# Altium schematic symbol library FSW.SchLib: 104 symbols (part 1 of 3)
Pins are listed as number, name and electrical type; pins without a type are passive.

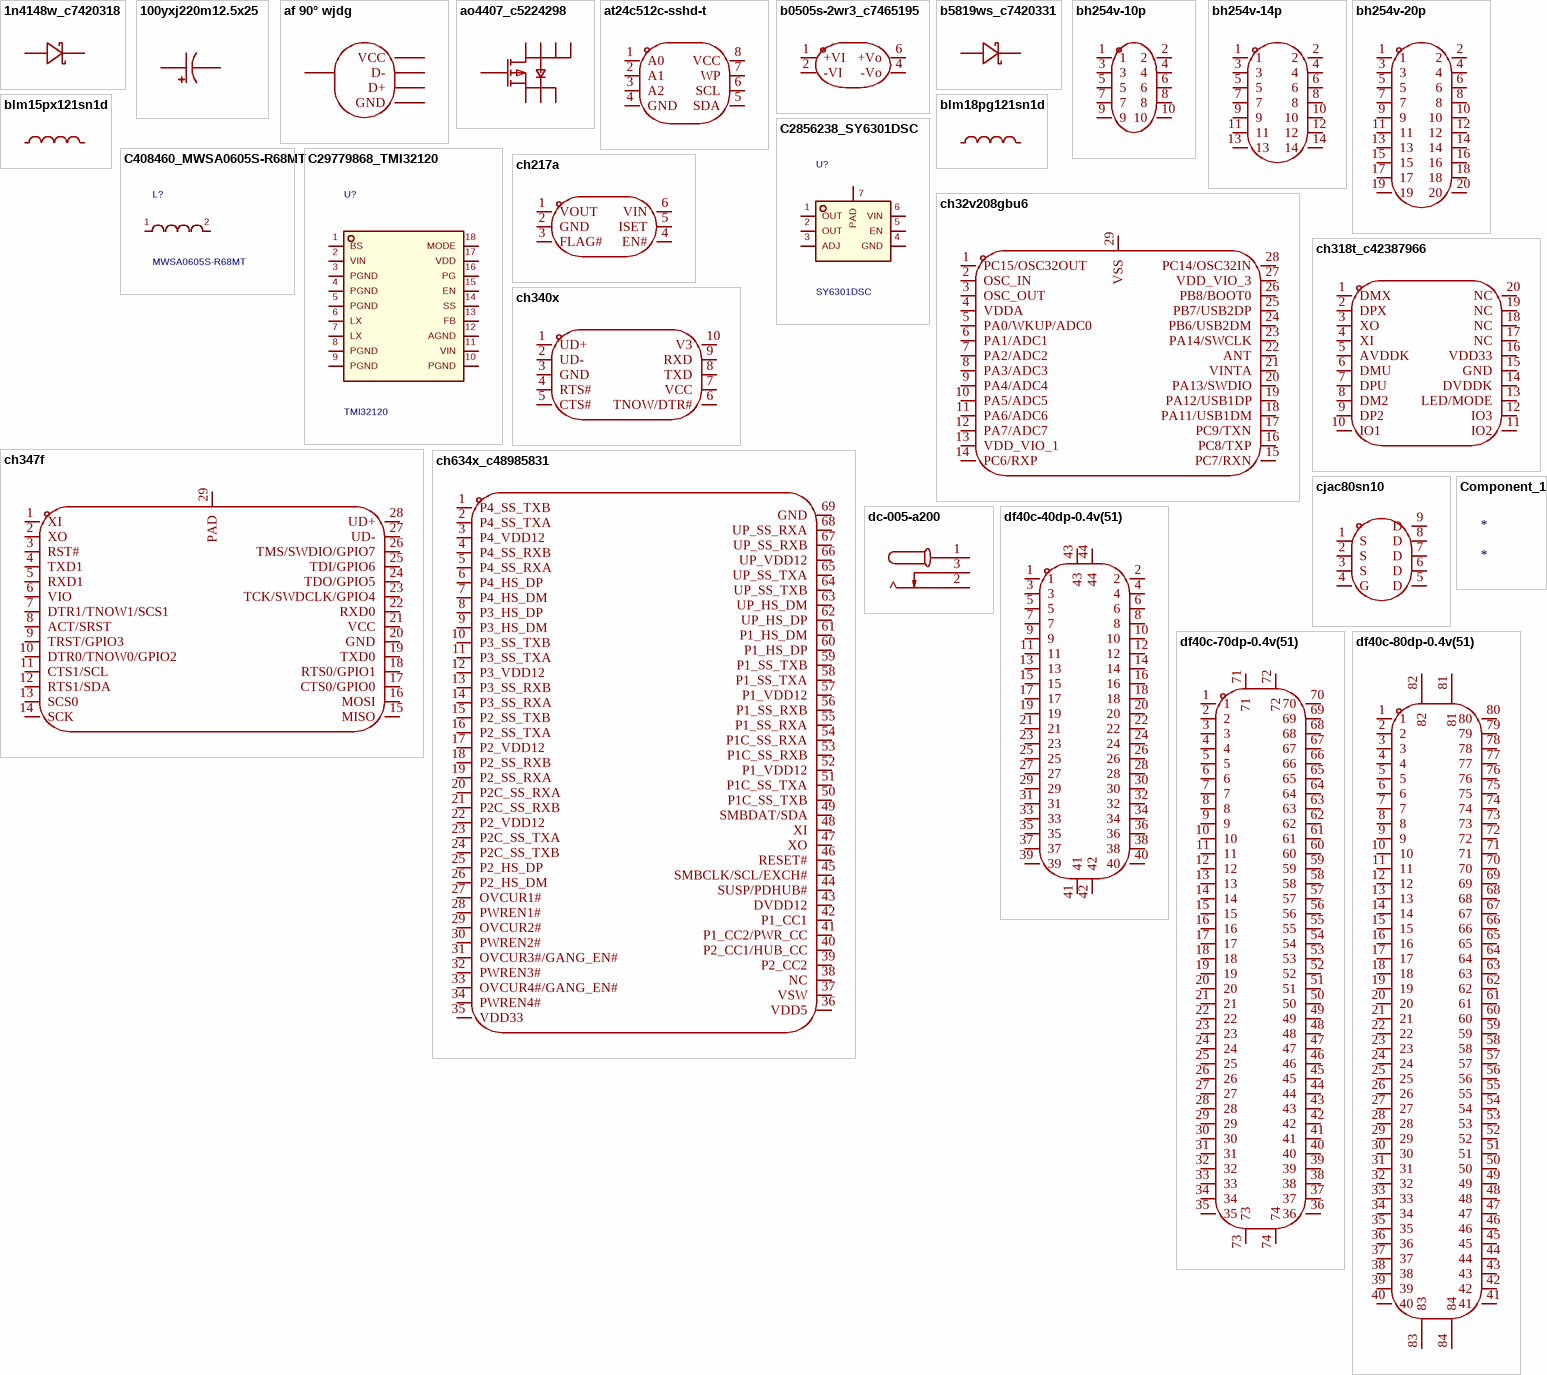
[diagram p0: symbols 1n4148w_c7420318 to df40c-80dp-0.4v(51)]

## 1n4148w_c7420318
designator D??  (value not drawn)
二极管配置:独立式;整流电流:150mA;直流反向耐压(Vr):100V;正向压降(Vf):1.25V@150mA;反向恢复时间(Trr):4ns;; Manufacturer: R+O(宏嘉诚); AddInBom: yes; ModelId: 5054d9b7be8b429dad093a54b517b4dd; ModelName: SOD-123_L2.7-W1.6-LS3.7-FD; ModelTransform: 145.669,61.024,0,0,0,0,0,0,0; Diode Configuration: 独立式; Pd - Power Dissipation: 400mW; Current - Rectified: 150mA; Voltage - DC Reverse(Vr): 100V; Non-Repetitive Peak Forward Surge Current: 2A; Reverse Leakage Current (Ir): 1uA@75V; Reverse Recovery Time (trr): 4ns; Operating Junction Temperature Range: -55℃~+150℃
footprint SOD-123_L2.7-W1.6-LS3.7-FD
pins: 1 A, 2 K

## 100yxj220m12.5x25
designator C??  (value not drawn)
容值:220uF;精度:±20%;额定电压:100V;纹波电流:1.62A@100kHz;等效串联电阻(ESR):-;; Manufacturer: Rubycon(红宝石); AddInBom: yes; ModelId: 968d8ff988964aab8919b46a6a737be2; ModelName: CAP-TH_D12.5-H20.0-P5.00; ModelTransform: 492.5187,492.11201,0,0,0,0,0,0,-137.795; Value: 220uF; Tolerance: ±20%; Voltage Rating: 100V; Pin Spacing: 5mm; Lifetime: 10000hrs@105℃
footprint CAP-TH_BD12.5-P5.00-D0.6-FD
pins: 1, 2

## af 90° wjdg
designator USB??  (value not drawn)
连接器类型:Type-A;协议标准:USB 2.0;公母:母;安装方式:弯插;触点数量:4P;端口数量:1;额定电流 - 电源:1.5A;工作温度:-25℃~+85℃;; Manufacturer: SHOU HAN(首韩); AddInBom: yes; ModelId: 268f7f19b8674295a50f5e7a4a3dee80; ModelName: USB-A-TH_4P-L14.5-W14.0-H7.6-S2.71; ModelTransform: 610.19406,551.18,0,0,0,0,0,-192.915,-149.606; Connector Type: Type-A; Protocol Standard: USB 2.0; Gender: 母; Number of Contacts: 4P; Number of Ports: 1; Current Rating-Power: 1.5A; Voltage Rating: 30V; Connect-Disconnect Life: 5千次; Detection color: 白色
footprint USB-A-TH_AF-WJDG
pins: 1 VCC, 2 D-, 3 D+, 4 GND, 5 SHLD

## ao4407_c5224298
designator Q??  (value not drawn)
数量:1个P沟道;漏源电压(Vdss):30V;连续漏极电流(Id):12A;导通电阻(RDS(on)):9.5mΩ@10V;耗散功率(Pd):3.1W;阈值电压(Vgs(th)):1.5V@250uA;; Manufacturer: ElecSuper(静芯); ManufacturerPart: AO4407; AddInBom: yes; ModelId: ca0cccb852be401a81142c6d2d7c8054; ModelName: SOIC-8_L4.9-W3.8-P1.27-LS6.0-BL; ModelTransform: 192.913,236.22,0,0,0,0,-0.002,0,0; Number: 1个P沟道; Drain to Source Voltage: 30V; Current - Continuous Drain(Id): 12A; Pd - Power Dissipation: 3.1W; Gate Charge(Qg): 46nC@10V; Input Capacitance(Ciss): 1.78nF; Reverse Transfer Capacitance (Crss@Vds): 200pF; Type: P沟道; Output Capacitance(Coss): 235pF
footprint SOIC-8_L4.9-W3.8-P1.27-LS6.0-BL
pins: 1 S, 2 S, 3 S, 4 G, 5 D, 6 D, 7 D, 8 D

## at24c512c-sshd-t
designator U??  (value not drawn)
接口类型:I2C;存储容量:512Kbit;时钟频率(fc):1MHz;; Manufacturer: MICROCHIP(美国微芯); AddInBom: yes; ModelId: e81d2f7d937b4a6ab1dca543ff5d56a4; ModelName: SOIC-8_L4.9-W3.9-H1.7-LS6.0-P1.27; ModelTransform: 192.913,236.22,0,0,0,0,0,0,0; Interface: I2C; Clock Frequency: 1MHz; Write Cycle Time(Tw): 5ms; Data Retention - TDR (Year): 40年; Write Cycle Endurance: 100万次; Voltage - Supply: 2.5V~5.5V
footprint SOIC-8_L4.9-W3.9-P1.27-LS6.0-BL
pins: 1 A0, 2 A1, 3 A2, 4 GND, 5 SDA, 6 SCL, 7 WP, 8 VCC

## b0505s-2wr3_c7465195
designator U??  (value not drawn)
DC-DC隔离电源模块:输入5V(4.5V~5.5V)@@输出5V 400mA 2W@@输出短路保护@@输入输出隔离耐压1.5KV@@SIP7; Manufacturer: EVISUN(易成); AddInBom: yes; ModelId: 14934276571d427a996fe673d734980f; ModelName: PWRM-TH_BXXXXS-2WR3; ModelTransform: 773.6205,277.5585,0,0,0,0,49.409,-102.953,-157.48; Number of Outputs: 1; Output Power: 2W; Conversion Efficiency: 88%; Output Voltage: 5V; Capacitive Load(Max): 2400uF; Isolation Voltage(Vrms): 1.5kV; Value: 200kHz~340kHz; Quiescent Supply Current: 8mA; Ripple Noise: 75mVp-p; Voltage Regulation: 非稳压型
footprint PWRM-TH_BXXXXS-2WR3
pins: 1 +VI, 2 -VI, 4 -Vo, 6 +Vo

## b5819ws_c7420331
designator D??  (value not drawn)
二极管配置:独立式;正向压降(Vf):600mV@1.0A;直流反向耐压(Vr):40V;整流电流:1A;; Manufacturer: R+O(宏嘉诚); AddInBom: yes; ModelId: 0f2f330c645944df9245ac3c3fec3456; ModelName: SOD-323_L1.7-W1.3-LS2.5-FD; ModelTransform: 98.425,49.2125,0,180,0,0,0,0,0; Diode Configuration: 独立式; Voltage - DC Reverse(Vr): 40V; Current - Rectified: 1A; Reverse Leakage Current (Ir): 1mA@40V; Operating Junction Temperature Range: -55℃~+150℃; Non-Repetitive Peak Forward Surge Current: 10A
footprint SOD-323_L1.7-W1.3-LS2.5-FD
pins: 1 A, 2 K

## bh254v-10p
designator CN??  (value not drawn)
连接器类型:简牛座;间距:2.54mm;结构:2x5P;额定电流:3A;额定电压:250V;安装方式:直插;行距:2.54mm;排数:2;每排PIN数:5;工作温度:-40℃~+105℃;; Manufacturer: XFCN(兴飞); AddInBom: yes; ModelId: 46a83b98c0514e7caa52e3945452bfaa; ModelName: IDC-TH_10P-P2.54-V-R2-C5-S2.54; ModelTransform: 799.21498,350.0906,0,0,0,0,0,3.937,-129.921; Connector Type: 简牛座; Pitch: 2.54mm; Number of Positions or Pins: 2x5P; Current Rating: 3A; Voltage Rating (Max): 250V; Holder Type: 直插; Number of PINs Per Row: 5
footprint IDC-TH_10P-P2.54-V-R2-C5-S2.54
pins: 1, 2, 3, 4, 5, 6, 7, 8, 9, 10

## bh254v-14p
designator CN??  (value not drawn)
连接器类型:简牛座;间距:2.54mm;结构:2x7P;额定电流:3A;安装方式:直插;行距:2.54mm;排数:2;每排PIN数:7;触头材质:铜合金;工作温度:-40℃~+105℃;; Manufacturer: XFCN(兴飞); AddInBom: yes; ModelId: 1e191473481d43b08e40c7df32061c8c; ModelName: IDC-TH_14P-P2.54-V-R2-C7-S2.54; ModelTransform: 999.998,348.41478,0,0,0,0,0,3.937,-118.11; Connector Type: 简牛座; Pitch: 2.54mm; Number of Positions or Pins: 2x7P; Current Rating: 3A; Holder Type: 直插; Number of PINs Per Row: 7
footprint IDC-TH_14P-P2.54-V-R2-C7-S2.54
pins: 1, 2, 3, 4, 5, 6, 7, 8, 9, 10, 11, 12, 13, 14

## bh254v-20p
designator CN??  (value not drawn)
连接器类型:简牛座;间距:-;结构:2x10P;额定电流:3A;额定电压:250V;安装方式:直插;行距:2.54mm;排数:2;每排PIN数:10;触头材质:-;触头镀层:-;工作温度:-40℃~+105℃;; Manufacturer: XFCN(兴飞); AddInBom: yes; ModelId: f758914ec7d246748ac341cdbdaac489; ModelName: CONN-TH_20P-P2.54_BH254V-20P; ModelTransform: 1299.214,350.0906,0,0,0,0,0,1.968,-127.953; Connector Type: 简牛座; Number of Positions or Pins: 2x10P; Current Rating: 3A; Voltage Rating (Max): 250V; Holder Type: 直插; Row Spacing: 2.54mm; Number of PINs Per Row: 10
footprint CONN-TH_20P-P2.54_BH254V-20P
pins: 1, 2, 3, 4, 5, 6, 7, 8, 9, 10, 11, 12, 13, 14, 15, 16, 17, 18, 19, 20

## blm15px121sn1d
designator L??  (value not drawn)
阻抗@频率:120Ω@100MHz;误差:±25%;直流电阻(DCR):55mΩ;; Manufacturer: muRata(村田); AddInBom: yes; ModelId: d8d36575a3234d4790bfa765c88664a7; ModelName: L0402_L1.0-W0.5-H0.5_BEAD; ModelTransform: 39.37,19.685,0,0,0,0,0,0.0005,0; Tolerance: ±25%; DC Resistance(DCR): 55mΩ; Current Rating: 2A; Number of Circuits: 1
footprint L0402
pins: 1, 2

## blm18pg121sn1d
designator L??  (value not drawn)
阻抗@频率:120Ω@100MHz;误差:±25%;直流电阻(DCR):50mΩ;; Manufacturer: muRata(村田); Symbol: BLM18PG121SN1D_C14709; AddInBom: yes; ModelId: 2bc5ec593d464d6ba9807aec0b5673c2; ModelName: L0603_L1.6-W0.8-H0.5_BEAD; ModelTransform: 62.992,31.496,0,180,0,0,0.094,0.629,0; Tolerance: ±25%; DC Resistance(DCR): 50mΩ; Current Rating: 2A; Number of Circuits: 1
footprint L0603
pins: 1, 2

## C408460_MWSA0605S-R68MT
designator L?, comment MWSA0605S-R68MT
MWSA0605S-R68MT [C408460]; Manufacturer: Sunlord(顺络); Symbol: C408460_MWSA0605S-R68MT; Value: 680nH; Library Source: JLCEDA/EasyEDA Official Library; https://lceda.cn/ ; https://easyeda.com/
footprint C408460_IND-SMD_L7_0-W6_6
pins: 1, 2

## C2856238_SY6301DSC
designator U?, comment SY6301DSC
SY6301DSC [C2856238]; Manufacturer: Silergy(矽力杰); Symbol: C2856238_SY6301DSC; Library Source: JLCEDA/EasyEDA Official Library; https://lceda.cn/ ; https://easyeda.com/
footprint C2856238_WDFN-6_L3_0-W3_0-P0_95
pins: 1 OUT, 2 OUT, 3 ADJ, 4 GND, 5 EN, 6 VIN, 7 PAD

## C29779868_TMI32120
designator U?, comment TMI32120
TMI32120 [C29779868]; Manufacturer: TMI(拓尔微); Symbol: C29779868_TMI32120; Library Source: JLCEDA/EasyEDA Official Library; https://lceda.cn/ ; https://easyeda.com/
footprint C29779868_VQFN-18_L3_5-W3_5-P0_
pins: 1 BS, 2 VIN, 3 PGND, 4 PGND, 5 PGND, 6 LX, 7 LX, 8 PGND, 9 PGND, 10 PGND, 11 VIN, 12 AGND, 13 FB, 14 SS, 15 EN, 16 PG, 17 VDD, 18 MODE

## ch32v208gbu6
designator U??  (value not drawn)
CH32V系列是基于青芯32位RISC-V设计的工业级通用微控制器。整个系列产品采用硬件堆栈区、快速中断进入等设计，相比标准大大提高了中断响应速度。CH32V208配备V4C内核，增加了内存保护功能并减少了硬件除法周期。在产品特性方面，它支持144MHz主频零等待操作。该系列集成了2Mbps低功耗蓝牙BLE通信模块、10M以太网MAC+PHY模块、USB2.0全速设备 + 主机/设备接口、CAN控制器等。; Manufacturer: WCH(南京沁恒); AddInBom: yes; ModelId: ea8b28b44f5d42878c4615c9108a8123; ModelName: QFN-28_L4.0-W4.0-P0.40-BL-EP2.8; ModelTransform: 157.48,157.48,0,0,0,0,0,0,0
footprint QFN-28_L4.0-W4.0-P0.40-BL-EP2.8
pins: 1 PC15/OSC32OUT, 2 OSC_IN, 3 OSC_OUT, 4 VDDA, 5 PA0/WKUP/ADC0, 6 PA1/ADC1, 7 PA2/ADC2, 8 PA3/ADC3, 9 PA4/ADC4, 10 PA5/ADC5, 11 PA6/ADC6, 12 PA7/ADC7, 13 VDD_VIO_1, 14 PC6/RXP, 15 PC7/RXN, 16 PC8/TXP, 17 PC9/TXN, 18 PA11/USB1DM, 19 PA12/USB1DP, 20 PA13/SWDIO, 21 VINTA, 22 ANT, 23 PA14/SWCLK, 24 PB6/USB2DM, 25 PB7/USB2DP, 26 PB8/BOOT0, 27 VDD_VIO_3, 28 PC14/OSC32IN, 29 VSS

## ch217a
designator U??  (value not drawn)
类型:负载开关;通道数:1;输入控制逻辑:低电平有效;工作电压:2.7V~5.5V;最大连续电流:2.7A;导通电阻:70mΩ;; Manufacturer: WCH(南京沁恒); AddInBom: yes; ModelId: f198fe6923cc4b1fabccb73198a22cca; ModelName: SOT-23-6_L2.9-W1.7-P0.95-LS2.8-BL; ModelTransform: 114.173,110.236,0,0,0,0,0,0,0; Number of Channels: 1; Control Input Logic: 低电平有效; Maximum Continuous Current: 2.7A; RDS(on): 70mΩ
footprint SOT-23-6_L2.9-W1.7-P0.95-LS2.8-BL
pins: 1 VOUT, 2 GND, 3 FLAG#, 4 EN#, 5 ISET, 6 VIN

## ch318t_c42387966
designator U??  (value not drawn)
是高速USB信号隔离和传输距离延长控制芯片，支持电容耦合或者网络变压器耦合，不但实现了对USB信号的隔离，同时实现了对USB信号的实时中转和传输距离延长。此外，芯片自身带有USBHUB功能，上行端口支持USB2.0高速，下行端口支持USB2.0高速480Mbps、全速12Mbps和低速1.5Mbps。可以用于高速USB信号隔离、隔离HUB、延长HUB等。; Manufacturer: WCH(南京沁恒); ManufacturerPart: CH318T; AddInBom: yes; ModelId: c491f68934b34c649df5890a1d97cd0f; ModelName: TSSOP-20_L6.5-W4.4-H1.0-LS6.4-P0.65; ModelTransform: 251.969,255.906,0,90,0,0,0.0005,0,0; Protocol: USB 1.1；USB 2.0; Data Rate(Max): 480Mbit/s; Voltage - Supply: 3.3V
footprint TSSOP-20_L6.5-W4.4-P0.65-LS6.4-BL
pins: 1 DMX, 2 DPX, 3 XO, 4 XI, 5 AVDDK, 6 DMU, 7 DPU, 8 DM2, 9 DP2, 10 IO1, 11 IO2, 12 IO3, 13 LED/MODE, 14 DVDDK, 15 GND, 16 VDD33, 17 NC, 18 NC, 19 NC, 20 NC

## ch340x
designator U??  (value not drawn)
应用功能:USB转串口；USB转并口;USB协议版本:USB 2.0;通道数:-;数据速率:2Mbps;; Manufacturer: WCH(南京沁恒); AddInBom: yes; ModelId: b42a31f9e1fa4643bc7ea573b9bba7ed; ModelName: MSOP-10_L3.0-W3.0-H1.1-LS5.0-P0.50; ModelTransform: 118.11,196.85,0,0,0,0,0,0,0; USB Protocol: USB 2.0; Voltage - Supply: 3.3V；5V; Data Rate: 2Mbps
footprint MSOP-10_L3.0-W3.0-P0.50-LS5.0-BL
pins: 1 UD+, 2 UD-, 3 GND, 4 RTS#, 5 CTS#, 6 TNOW/DTR#, 7 VCC, 8 TXD, 9 RXD, 10 V3

## ch347f
designator U??  (value not drawn)
应用功能:USB转UART；USB转SPI；USB转SWD；USB转I2C；USB转JTAG;USB协议版本:USB 2.0;通道数:2;数据速率:480Mbps;; Manufacturer: WCH(南京沁恒); AddInBom: yes; ModelId: 026209c2d38043429298993ef2ab37e8; ModelName: QFN-28_L4.0-W4.0-P0.40-BL-EP2.7; ModelTransform: 158.267,158.267,0,0,0,0,0,0,0; USB Protocol: USB 2.0; Number of Channels: 2; Voltage - Supply: 3V~3.6V; Current - Supply: 38mA; Quiescent Supply Current: 260uA
footprint QFN-28_L4.0-W4.0-P0.40-BL-EP2.7
pins: 1 XI, 2 XO, 3 RST#, 4 TXD1, 5 RXD1, 6 VIO, 7 DTR1/TNOW1/SCS1, 8 ACT/SRST, 9 TRST/GPIO3, 10 DTR0/TNOW0/GPIO2, 11 CTS1/SCL, 12 RTS1/SDA, 13 SCS0, 14 SCK, 15 MISO, 16 MOSI, 17 CTS0/GPIO0, 18 RTS0/GPIO1, 19 TXD0, 20 GND, 21 VCC, 22 RXD0, 23 TCK/SWDCLK/GPIO4, 24 TDO/GPIO5, 25 TDI/GPIO6, 26 TMS/SWDIO/GPIO7, 27 UD-, 28 UD+, 29 PAD

## ch634x_c48985831
designator U??  (value not drawn)
符合USB3.2 Gen1协议规范的4端口USB超高速HUB控制器芯片,CH634X内置两组Type-C双通道USB3.0 PHY和双PD PHY，原生支持Type-C正反插自适应，原生支持PDHUB、Type-C15W和PD100W快充。; Manufacturer: WCH(南京沁恒); ManufacturerPart: CH634X; AddInBom: yes; ModelId: 72236333b5b14e54ba405b685275d4d4; ModelName: QFN-68_L8.0-W8.0-H0.8-P0.40-BL-EP; ModelTransform: 314.96,314.96,0,90,0,0,0,0,0; USB Protocol: USB 3.2; Data Rate: 5Gbps; Voltage - Supply: 3.3V；1.23V; Number of Channels: 4
footprint QFN-68_L8.0-W8.0-P0.40-BL-EP6.2
pins: 1 P4_SS_TXB, 2 P4_SS_TXA, 3 P4_VDD12, 4 P4_SS_RXB, 5 P4_SS_RXA, 6 P4_HS_DP, 7 P4_HS_DM, 8 P3_HS_DP, 9 P3_HS_DM, 10 P3_SS_TXB, 11 P3_SS_TXA, 12 P3_VDD12, 13 P3_SS_RXB, 14 P3_SS_RXA, 15 P2_SS_TXB, 16 P2_SS_TXA, 17 P2_VDD12, 18 P2_SS_RXB, 19 P2_SS_RXA, 20 P2C_SS_RXA, 21 P2C_SS_RXB, 22 P2_VDD12, 23 P2C_SS_TXA, 24 P2C_SS_TXB, 25 P2_HS_DP, 26 P2_HS_DM, 27 OVCUR1#, 28 PWREN1#, 29 OVCUR2#, 30 PWREN2#, 31 OVCUR3#/GANG_EN#, 32 PWREN3#, 33 OVCUR4#/GANG_EN#, 34 PWREN4#, 35 VDD33, 36 VDD5, 37 VSW, 38 NC, 39 P2_CC2, 40 P2_CC1/HUB_CC, 41 P1_CC2/PWR_CC, 42 P1_CC1, 43 DVDD12, 44 SUSP/PDHUB#, 45 SMBCLK/SCL/EXCH#, 46 RESET#, 47 XO, 48 XI, 49 SMBDAT/SDA, 50 P1C_SS_TXB, 51 P1C_SS_TXA, 52 P1_VDD12, 53 P1C_SS_RXB, 54 P1C_SS_RXA, 55 P1_SS_RXA, 56 P1_SS_RXB, 57 P1_VDD12, 58 P1_SS_TXA, 59 P1_SS_TXB, 60 P1_HS_DP, 61 P1_HS_DM, 62 UP_HS_DP, 63 UP_HS_DM, 64 UP_SS_TXB, 65 UP_SS_TXA, 66 UP_VDD12, 67 UP_SS_RXB, 68 UP_SS_RXA, 69 GND

## cjac80sn10
designator Q??  (value not drawn)
数量:1个N沟道;漏源电压(Vdss):100V;连续漏极电流(Id):80A;导通电阻(RDS(on)):10.5mΩ@4.5V;耗散功率(Pd):100W;阈值电压(Vgs(th)):2.5V;; Manufacturer: CJ(江苏长电/长晶); AddInBom: yes; ModelId: 64dd0a0ad16f4146a485008a6fd3b168; ModelName: PDFN-8_L5.8-W5.0-P1.27-LS6.0-BL; ModelTransform: 193.7004,238.189,0,0,0,0,0,0,0; Number: 1个N沟道; Drain to Source Voltage: 100V; Current - Continuous Drain(Id): 80A; Pd - Power Dissipation: 100W; Gate Threshold Voltage (Vgs(th)): 2.5V; Gate Charge(Qg): 100nC@10V; Input Capacitance(Ciss): 3.15nF; Reverse Transfer Capacitance (Crss@Vds): 8pF; Type: N沟道; Output Capacitance(Coss): 650pF
footprint PDFN-8_L5.8-W5.0-P1.27-LS6.0-BL
pins: 1 S, 2 S, 3 S, 4 G, 5 D, 6 D, 7 D, 8 D, 9 D

## Component_1
designator *

## dc-005-a200
designator DC??  (value not drawn)
连接器类型:DC电源插座;安装方式:弯插;触点内径:2mm;触点外径:6.4mm;额定电流:3A;额定电压:30V;工作温度:-20℃~+70℃;; Manufacturer: XUNPU(讯普); AddInBom: yes; ModelId: 1321cdbe1dc84555a9684967491c8670; ModelName: DC-IN-TH_DC-005-A200; ModelTransform: 553.149,368.14887,0,0,0,0,-137.795,85.63,-161.417; Connector Type: DC电源插座; Inside Contact Diameter: 2mm; Outside Contact Diameter: 6.4mm; Current Rating: 3A; Voltage Rating (Max): 30V
footprint DC-IN-TH_DC-005-A200
pins: 1, 2, 3

## df40c-40dp-0.4v(51)
designator CN??  (value not drawn)
总PIN数:40P;间距:0.4mm;安装方式:立贴;排数:2;额定电流:300mA;工作温度:-35℃~+85℃;; Manufacturer: HRS(广濑); AddInBom: yes; ModelId: b56a478347b2449391f6835926ba63be; ModelName: CONN-SMD_DF40C-40DP-0.4V; ModelTransform: 374.802,116.9289,0,0,0,0,0,0,0; Pitch: 0.4mm; Gender: 公; Current Rating: 300mA; Voltage Rating: 30V; Connection Type: 槽型对接
footprint CONN-SMD_DF40C-40DP-0.4V
pins: 1, 2, 3, 4, 5, 6, 7, 8, 9, 10, 11, 12, 13, 14, 15, 16, 17, 18, 19, 20, 21, 22, 23, 24, 25, 26, 27, 28, 29, 30, 31, 32, 33, 34, 35, 36, 37, 38, 39, 40, 41, 42, 43, 44

## df40c-70dp-0.4v(51)
designator CN??  (value not drawn)
总PIN数:70P;间距:0.4mm;安装方式:立贴;排数:2;额定电流:300mA;工作温度:-35℃~+85℃;; Manufacturer: HRS(广濑); AddInBom: yes; ModelId: 82d53555e99e41b288893f89f04491cd; ModelName: CONN-SMD_DF40C-70DP-0.4V-51; ModelTransform: 611.0224,116.9289,0,0,0,0,-0.002,0,0; Pitch: 0.4mm; Gender: 公; Current Rating: 300mA; Voltage Rating: 30V; Connection Type: 槽型对接
footprint CONN-SMD_DF40C-70DP-0.4V-51
pins: 1, 2, 3, 4, 5, 6, 7, 8, 9, 10, 11, 12, 13, 14, 15, 16, 17, 18, 19, 20, 21, 22, 23, 24, 25, 26, 27, 28, 29, 30, 31, 32, 33, 34, 35, 36, 37, 38, 39, 40, 41, 42, 43, 44, 45, 46, 47, 48, 49, 50, 51, 52, 53, 54, 55, 56, 57, 58, 59, 60, 61, 62, 63, 64, 65, 66, 67, 68, 69, 70, 71, 72, 73, 74

## df40c-80dp-0.4v(51)
designator CN??  (value not drawn)
总PIN数:80P;间距:0.4mm;安装方式:立贴;排数:2;额定电流:300mA;工作温度:-35℃~+85℃;; Manufacturer: HRS(广濑); AddInBom: yes; ModelId: b7b59d0264e248c0b3a3a957f3f9b089; ModelName: CONN-SMD_DF40C-80DP-0.4V-51; ModelTransform: 689.80173,116.9289,0,0,0,0,0,0,0; Pitch: 0.4mm; Gender: 公; Current Rating: 300mA; Connection Type: 槽型对接
footprint CONN-SMD_DF40C-80DP-0.4V-51
pins: 1, 2, 3, 4, 5, 6, 7, 8, 9, 10, 11, 12, 13, 14, 15, 16, 17, 18, 19, 20, 21, 22, 23, 24, 25, 26, 27, 28, 29, 30, 31, 32, 33, 34, 35, 36, 37, 38, 39, 40, 41, 42, 43, 44, 45, 46, 47, 48, 49, 50, 51, 52, 53, 54, 55, 56, 57, 58, 59, 60, 61, 62, 63, 64, 65, 66, 67, 68, 69, 70, 71, 72, 73, 74, 75, 76, 77, 78, 79, 80, 81, 82, 83, 84

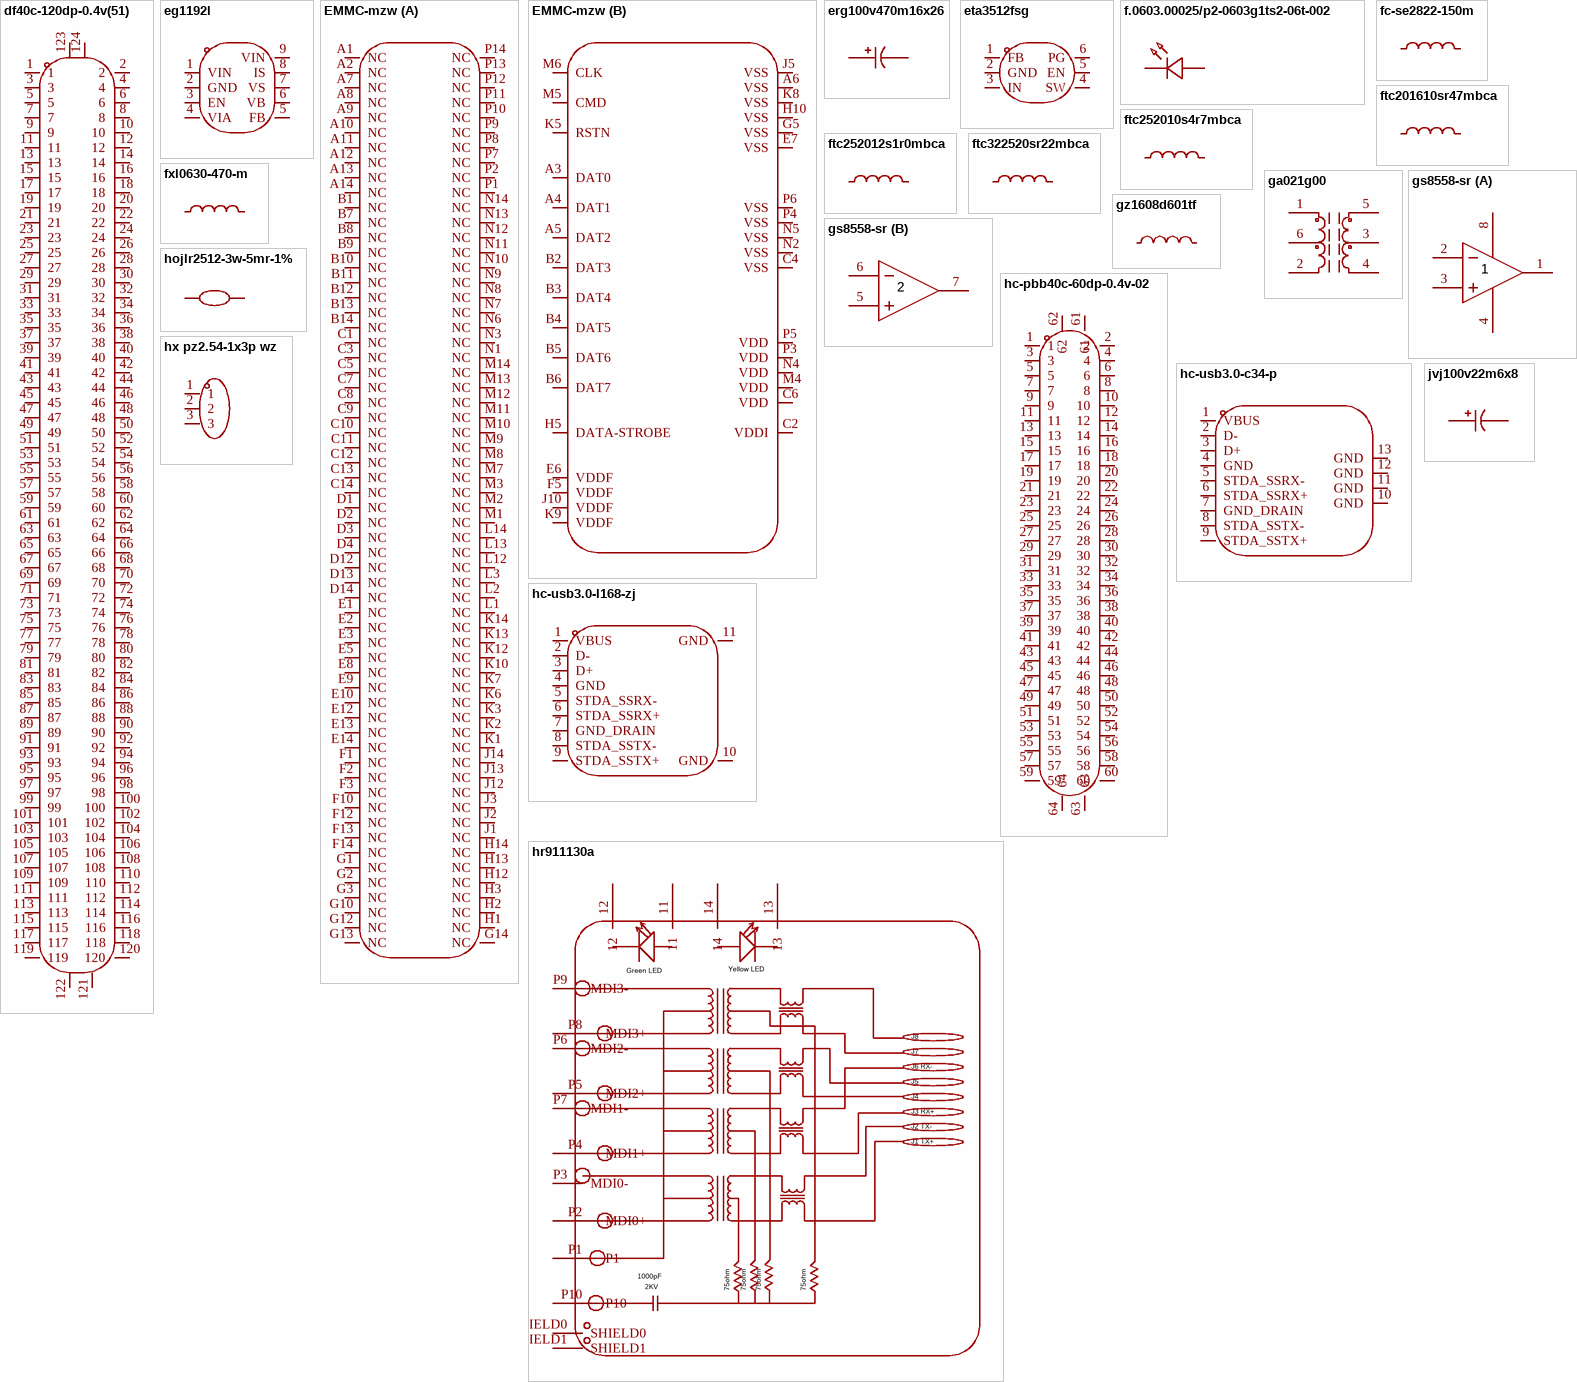
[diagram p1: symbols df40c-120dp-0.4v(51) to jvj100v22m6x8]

## df40c-120dp-0.4v(51)
designator CN??  (value not drawn)
总PIN数:120P;间距:0.4mm;安装方式:立贴;排数:2;额定电流:300mA;工作温度:-35℃~+85℃;; Manufacturer: HRS(广濑); AddInBom: yes; ModelId: c4795e4c1e12425ebd29485652b72dd8; ModelName: CONN-SMD_120P-P0.40_DF40C-120DP-0.4V-51; ModelTransform: 1005.11606,116.929,0,0,0,0,0,0,0; Pitch: 0.4mm; Gender: 公; Current Rating: 300mA; Voltage Rating: 30V; Connection Type: 槽型对接
footprint CONN-SMD_120P-P0.40_DF40C-120DP-0.4V-51
pins: 1, 2, 3, 4, 5, 6, 7, 8, 9, 10, 11, 12, 13, 14, 15, 16, 17, 18, 19, 20, 21, 22, 23, 24, 25, 26, 27, 28, 29, 30, 31, 32, 33, 34, 35, 36, 37, 38, 39, 40, 41, 42, 43, 44, 45, 46, 47, 48, 49, 50, 51, 52, 53, 54, 55, 56, 57, 58, 59, 60, 61, 62, 63, 64, 65, 66, 67, 68, 69, 70, 71, 72, 73, 74, 75, 76, 77, 78, 79, 80, 81, 82, 83, 84, 85, 86, 87, 88, 89, 90, 91, 92, 93, 94, 95, 96, 97, 98, 99, 100, 101, 102, 103, 104, 105, 106, 107, 108, 109, 110, 111, 112, 113, 114, 115, 116, 117, 118, 119, 120, 121, 122, 123, 124

## eg1192l
designator U??  (value not drawn)
功能类型:降压型;工作电压:10V~100V;输出电压:-;输出电流:3A;输出类型:可调;; Manufacturer: EG(屹晶微); AddInBom: yes; ModelId: d3e00daa36c445139c055a3b9efb85d2; ModelName: ESOP-8_L4.9-W3.9-H1.6-LS6.0-P1.27; ModelTransform: 240.157,192.913,0,90,0,0,0,0,0; Function: 降压型; Output Current: 3A; Frequency - Switching: 110kHz; Synchronous Rectifier: 否; Number of Outputs: 1; Topology: 降压式; Quiescent Current: 2mA; Switch tube (built-in/external): 内置; Output Type: 可调
footprint ESOP-8_L4.9-W3.9-P1.27-LS6.0-BL-EP
pins: 1 VIN, 2 GND, 3 EN, 4 VIA, 5 FB, 6 VB, 7 VS, 8 IS, 9 VIN

## EMMC-mzw
designator ??  (value not drawn)
part A pins: A1 NC, A2 NC, A7 NC, A8 NC, A9 NC, A10 NC, A11 NC, A12 NC, A13 NC, A14 NC, B1 NC, B7 NC, B8 NC, B9 NC, B10 NC, B11 NC, B12 NC, B13 NC, B14 NC, C1 NC, C3 NC, C5 NC, C7 NC, C8 NC, C9 NC, C10 NC, C11 NC, C12 NC, C13 NC, C14 NC, D1 NC, D2 NC, D3 NC, D4 NC, D12 NC, D13 NC, D14 NC, E1 NC, E2 NC, E3 NC, E5 NC, E8 NC, E9 NC, E10 NC, E12 NC, E13 NC, E14 NC, F1 NC, F2 NC, F3 NC, F10 NC, F12 NC, F13 NC, F14 NC, G1 NC, G2 NC, G3 NC, G10 NC, G12 NC, G13 NC, G14 NC, H1 NC, H2 NC, H3 NC, H12 NC, H13 NC, H14 NC, J1 NC, J2 NC, J3 NC, J12 NC, J13 NC, J14 NC, K1 NC, K2 NC, K3 NC, K6 NC, K7 NC, K10 NC, K12 NC, K13 NC, K14 NC, L1 NC, L2 NC, L3 NC, L12 NC, L13 NC, L14 NC, M1 NC, M2 NC, M3 NC, M7 NC, M8 NC, M9 NC, M10 NC, M11 NC, M12 NC, M13 NC, M14 NC, N1 NC, N3 NC, N6 NC, N7 NC, N8 NC, N9 NC, N10 NC, N11 NC, N12 NC, N13 NC, N14 NC, P1 NC, P2 NC, P7 NC, P8 NC, P9 NC, P10 NC, P11 NC, P12 NC, P13 NC, P14 NC
part B pins: A3 DAT0, A4 DAT1, A5 DAT2, A6 VSS, B2 DAT3, B3 DAT4, B4 DAT5, B5 DAT6, B6 DAT7, C2 VDDI, C4 VSS, C6 VDD, E6 VDDF, E7 VSS, F5 VDDF, G5 VSS, H5 DATA-STROBE, H10 VSS, J5 VSS, J10 VDDF, K5 RSTN, K8 VSS, K9 VDDF, M4 VDD, M5 CMD, M6 CLK, N2 VSS, N4 VDD, N5 VSS, P3 VDD, P4 VSS, P5 VDD, P6 VSS

## erg100v470m16x26
designator C??  (value not drawn)
容值:470uF;精度:±20%;额定电压:100V;纹波电流:1.62A@100kHz;等效串联电阻(ESR):45mΩ@100kHz;; Manufacturer: JIERR(捷而瑞); AddInBom: yes; ModelId: a842c2f395fb43008390029215713635; ModelName: CAP-TH_BD16.0-P7.5-D0.8-FD; ModelTransform: 629.92,629.92,0,0,0,0,0,0,-196.85; Value: 470uF; Tolerance: ±20%; Voltage Rating: 100V; Pin Spacing: 7.5mm; Lifetime: 2000hrs@105℃
footprint CAP-TH_BD16.0-P7.50-D0.8-FD
pins: 1, 2

## eta3512fsg
designator U??  (value not drawn)
功能类型:降压型;工作电压:2.5V~5.5V;输出电压:600mV~5.5V;输出电流:3A;输出类型:可调;; Manufacturer: ETA(钰泰); AddInBom: yes; ModelId: 6c48915c55ca481897faee5dfab5b527; ModelName: SOT-563-6_L1.6-W1.2-P0.5-LS1.6-BL; ModelTransform: 62.992,62.992,0,0,0,0,0,0,0; Function: 降压型; Output Current: 3A; Frequency - Switching: 2MHz; Synchronous Rectifier: 是; Number of Outputs: 1; Topology: 降压式; Quiescent Current: 50uA; Switch tube (built-in/external): 内置; Output Type: 可调
footprint SOT-563-6_L1.6-W1.2-P0.5-LS1.6-BL
pins: 1 FB, 2 GND, 3 IN, 4 SW, 5 EN, 6 PG

## f.0603.00025/p2-0603g1ts2-06t-002
designator LED??  (value not drawn)
灯头类型:1.6mmx0.8mm方形灯头;发光颜色:翠绿色;正向压降(Vf):2.6V~2.9V;功率:90mW;正向电流:30mA;波长:520nm~525nm;二极管配置:独立二极管;透镜颜色:-;色温:-;发光强度:230mcd;发光角度:120°;载带方式:-;工作温度:-40℃~+85℃;; Manufacturer: TUOZHAN(拓展光电); AddInBom: yes; ModelId: 7761174b67d9475ab0dbce38062fb2f9; ModelName: LED0603-RD_GREEN; ModelTransform: 63.7794,31.496,0,0,0,0,0,0,0; Illumination Color: 翠绿色; Power(Watts): 90mW; Forward Current: 30mA; Peak Wavelength: 517nm; Diode Configuration: 独立二极管; Luminous Intensity: 230mcd; Viewing Angle: 120°
footprint LED0603-RD_GREEN
pins: 1 C, 2 A

## fc-se2822-150m
designator L??  (value not drawn)
电感值:15uH;精度:±20%;额定电流:30A;饱和电流(Isat):30.5A;类型:-;; Manufacturer: FC(方成); AddInBom: yes; ModelId: b1b8f7090fd941118d4b89044bfce1b2; ModelName: IND-TH_L28.0-W23.0_FC-SE2822; ModelTransform: 1102.36,905.51,0,0,0,0,0,0,-137.795; Value: 15uH; Tolerance: ±20%; Current Rating: 30A; Current - Saturation(Isat): 30.5A; DC Resistance(DCR): 3.5mΩ
footprint IND-TH_L28.0-W23.0_FC-SE2822
pins: 1, 2

## ftc201610sr47mbca
designator U??  (value not drawn)
小型化一体成型T-CORE，小体积，扁线工艺，感值小; Manufacturer: cjiang(长江微电); AddInBom: yes; ModelId: b394e7fcf39b47c8917c782d9e6cbcf8; ModelName: IND-SMD_L2.0-W1.6-H1.1; ModelTransform: 62.992,79.527,0,90,0,0,0,0,0
footprint IND-SMD_L2.0-W1.6
pins: 1, 2

## ftc252010s4r7mbca
designator L??  (value not drawn)
电感值:4.7uH;精度:±20%;额定电流:2A;饱和电流(Isat):2.6A;类型:-;; Manufacturer: cjiang(长江微电); AddInBom: yes; ModelId: e143e04106934774881cec608355723f; ModelName: IND-SMD_L2.5-W2.0-VLS252012CX-150M; ModelTransform: 98.504,78.819,0,0,0,0,-0.004,-0.003,0; Value: 4.7uH; Tolerance: ±20%; Current Rating: 2A; Current - Saturation(Isat): 2.6A; DC Resistance(DCR): 160mΩ
footprint IND-SMD_L2.5-W2.0-VLS252012CX-150M
pins: 1, 2

## ftc252012s1r0mbca
designator U??  (value not drawn)
小型化一体成型T-CORE，小体积，扁线工艺，感值小; Manufacturer: cjiang(长江微电); AddInBom: yes; ModelId: e143e04106934774881cec608355723f; ModelName: IND-SMD_L2.5-W2.0-VLS252012CX-150M; ModelTransform: 98.504,78.819,0,0,0,0,-0.004,-0.003,0
footprint IND-SMD_L2.5-W2.0-VLS252012CX-150M
pins: 1, 2

## ftc322520sr22mbca
designator L??  (value not drawn)
小型化一体成型T-CORE，小体积，扁线工艺，感值小; Manufacturer: cjiang(长江微电); AddInBom: yes; ModelId: d98eeba27e8b4be081b5c0f1ff3b2836; ModelName: IND-SMD_L3.2-W2.5-2; ModelTransform: 125.984,98.464,0,0,0,0,-0.004,0.005,0
footprint IND-SMD_L3.2-W2.5-2
pins: 1, 2

## fxl0630-470-m
designator L??  (value not drawn)
电感值:47uH;精度:±20%;额定电流:1.5A;饱和电流(Isat):2A;类型:一体成型电感;; Manufacturer: cjiang(长江微电); AddInBom: yes; ModelId: 6712504104d74f0ca01cd7d0df9965b7; ModelName: IND-SMD_L7.0-W6.6-H2.8_FXL0630; ModelTransform: 275.59,259.842,0,0,0,0,0,0,0; Value: 47uH; Tolerance: ±20%; Rated Current: 1.5A; Saturation Current (Isat): 2A; DC Resistance (DCR): 385mΩ; Type: 一体成型电感
footprint IND-SMD_L7.0-W6.6_FXL0630
pins: 1, 2

## ga021g00
designator U??  (value not drawn)
线路数:4;电感@频率:120uH@100kHz;阻抗@频率:-;直流电阻(DCR):1.2Ω;; Manufacturer: CND-tek(磁联达); AddInBom: yes; ModelId: 47185f9e5e204908b0c4690c3dbe201c; ModelName: FILTER-SMD_6P-L4.5-W3.4_GA021G00; ModelTransform: 181.18074,133.858,0,0,0,0,0.001,-0.001,0; Number of Lines: 4; Current Rating: 720mA; Voltage Withstand: 1.5kV; DC Resistance(DCR): 1.2Ω
footprint FILTER-SMD_6P-L4.5-W3.4_GA021G00
pins: 1, 2, 3, 4, 5, 6

## gs8558-sr
designator U??  (value not drawn)
放大器数:双路;增益带宽积(GBP):13MHz;输入偏置电流(Ib):100pA;输入失调电压(Vos):5uV;压摆率(SR):8V/us;轨到轨:轨到轨输入,轨到轨输出;; Manufacturer: Gainsil(聚洵); AddInBom: yes; ModelId: ca0cccb852be401a81142c6d2d7c8054; ModelName: SOIC-8_L4.9-W3.8-P1.27-LS6.0-BL; ModelTransform: 192.913,236.22,0,0,0,0,-0.002,0,0; Number of Channels: 双路; Gain Bandwidth Product: 13MHz; Ib - Input Bias Current: 100pA; Vos - Input Offset Voltage: 5uV; Common Mode Rejection Ratio(CMRR): 100dB; Slew Rate: 8V/us; Output Current: 109mA; Input Offset Voltage Drift(Vos TC): 27nV/℃; Quiescent Current(Iq): 1.3mA; Single Supply: 2.5V~5.5V; Dual Supply: 1.25V~2.75V；-2.75V~-1.25V; Maximum Power Supply Range (Vdd-Vss): 5.5V; Input Offset Current(Ios): 10pA
footprint SOIC-8_L4.9-W3.8-P1.27-LS6.0-BL
part A pins: 1 OUTA, 2 -INA, 3 +INA, 4 VSS, 8 VDD
part B pins: 5 +INB, 6 -INB, 7 OUTB

## gz1608d601tf
designator L??  (value not drawn)
阻抗@频率:600Ω@100MHz;误差:±25%;直流电阻(DCR):450mΩ;; Manufacturer: Sunlord(顺络); AddInBom: yes; ModelId: 2bc5ec593d464d6ba9807aec0b5673c2; ModelName: L0603_L1.6-W0.8-H0.5_BEAD; ModelTransform: 62.992,31.496,0,180,0,0,0.094,0.629,0; Tolerance: ±25%; DC Resistance(DCR): 450mΩ; Current Rating: 200mA; Number of Circuits: 1
footprint L0603
pins: 1, 2

## hc-pbb40c-60dp-0.4v-02
designator U??  (value not drawn)
总PIN数:60P;间距:0.4mm;安装方式:立贴;排数:2;额定电流:300mA;工作温度:-35℃~+85℃;; Manufacturer: HCTL(华灿天禄); AddInBom: yes; ModelId: 82528091938141959821919b9de32a18; ModelName: CONN-SMD_60P-P0.40_HCTL_HC-PBB40C-60DP-0.4V-02; ModelTransform: 532.28634,116.9289,0,0,0,0,0,0,0; Pitch: 0.4mm; Gender: 公; System Fit Height: 2.5mm；3mm；4mm；3.5mm；2mm；1.5mm; Current Rating: 300mA; Connection Type: 槽型对接
footprint CONN-SMD_60P-P0.40_HCTL_HC-PBB40C-60DP-0.4V-02
pins: 1, 2, 3, 4, 5, 6, 7, 8, 9, 10, 11, 12, 13, 14, 15, 16, 17, 18, 19, 20, 21, 22, 23, 24, 25, 26, 27, 28, 29, 30, 31, 32, 33, 34, 35, 36, 37, 38, 39, 40, 41, 42, 43, 44, 45, 46, 47, 48, 49, 50, 51, 52, 53, 54, 55, 56, 57, 58, 59, 60, 61, 62, 63, 64

## hc-usb3.0-c34-p
designator USB??  (value not drawn)
连接器类型:Type-A;协议标准:USB 3.0;公母:母;安装方式:沉板;触点数量:9P;端口数量:1;额定电流 - 电源:1.5A;工作温度:-25℃~+70℃;; Manufacturer: HC(虹成电子); AddInBom: yes; ModelId: 92e1373ddb204efd94833f18e4347812; ModelName: USB-3.0-A-SMD_HC-USB3.0-C34-P; ModelTransform: 610.235,559.054,0,0,0,0,0,-98.425,-133.858; Connector Type: Type-A; Protocol Standard: USB 3.0; Gender: 母; Number of Contacts: 9P; Number of Ports: 1; Current Rating-Power: 1.5A; Voltage Rating: 30V; Connect-Disconnect Life: 1.5千次; Detection color: 蓝色
footprint USB-3.0-A-SMD_HC-USB3.0-C34-P
pins: 1 VBUS, 2 D-, 3 D+, 4 GND, 5 STDA_SSRX-, 6 STDA_SSRX+, 7 GND_DRAIN, 8 STDA_SSTX-, 9 STDA_SSTX+, 10 GND, 11 GND, 12 GND, 13 GND

## hc-usb3.0-l168-zj
designator USB??  (value not drawn)
连接器类型:Type-A;协议标准:USB 3.0;公母:母;安装方式:弯插;触点数量:9P;端口数量:1;额定电流 - 电源:1.5A;工作温度:-25℃~+70℃;; Manufacturer: HC(虹成电子); AddInBom: yes; ModelId: bc0796d16d324bfcacd0bfc17bd253cb; ModelName: USB3.0-A-TH_HC-USB3.0-L168-ZJ; ModelTransform: 566.928,661.41998,0,0,0,0,-0.001,-204.722,-114.173; Connector Type: Type-A; Protocol Standard: USB 3.0; Gender: 母; Number of Contacts: 9P; Number of Ports: 1; Current Rating-Power: 1.5A; Voltage Rating: 30V; Connect-Disconnect Life: 1.5千次; Detection color: 蓝色
footprint USB3.0-A-TH_HC-USB3.0-L168-ZJ
pins: 1 VBUS, 2 D-, 3 D+, 4 GND, 5 STDA_SSRX-, 6 STDA_SSRX+, 7 GND_DRAIN, 8 STDA_SSTX-, 9 STDA_SSTX+, 10 GND, 11 GND

## hojlr2512-3w-5mr-1%
designator R??  (value not drawn)
电阻类型:采样电阻;阻值:5mΩ;精度:±1%;功率:3W;安装方式:贴片;; Manufacturer: Milliohm(毫欧); AddInBom: yes; ModelId: 2a92684014bd46c593e4aa7ce823c350; ModelName: RES-SMD_L6.4-W3.2-1; ModelTransform: 251.968,125.984,0,0,0,0,0,0,0; Value: 5mΩ; Tolerance: ±1%; Power(Watts): 3W; Mounting Sytle: 贴片
footprint RES-SMD_L6.4-W3.2-1
pins: 1, 2

## hr911130a
designator RJ??  (value not drawn)
连接器类型:RJ45插座;安装方式:弯插;端口数量:1;LED:带LED;屏蔽:有屏蔽;等级:-;触头材质:磷青铜;触头镀层:金;工作温度:0℃~+70℃;; Manufacturer: HANRUN(汉仁); AddInBom: yes; ModelId: 21112b2bcfef4316930bd636ff253b92; ModelName: RJ45-TH_HR911130A; ModelTransform: 635.432,838.62,0,180,0,0,0,88.937,-157.48; Connector Type: RJ45插座; Number of Ports: 1; LED: 带LED; Shielding: 有屏蔽; PoE: 不带PoE; Supplementary Features: 带十字脚
footprint RJ45-TH_HR911130A
pins: 11, 12, 13, 14, P1, P2 MDI0+, P3 MDI0-, P4 MDI1+, P5 MDI2+, P6 MDI2-, P7 MDI1-, P8 MDI3+, P9 MDI3-, P10, SHIELD0, SHIELD1

## hx pz2.54-1x3p wz
designator H??  (value not drawn)
插针结构:1x3P;间距:2.54mm;行距:-;圆针/方针:方针;安装方式:弯插;排数:单排;总PIN位数:3P;额定电流:3A;额定电压:1kV;配合针长度:6mm;塑高:2.5mm;端接针长度:3mm;触头材质:黄铜;触头镀层:金;工作温度:-40℃~+105℃;颜色:黑色;; Manufacturer: hanxia(韩下); AddInBom: yes; ModelId: 7301705287024e6b9bd3086961f275a1; ModelName: HDR-TH_3P-P2.54-H-M-W10.4-N; ModelTransform: 299.9994,405.511,0,0,0,0,0,-188.976,-118.11; Pin Structure: 1x3P; Pitch: 2.54mm; Circluar Pins/Square Pins: 方针; Current Rating: 3A; Voltage Rating (Max): 1kV
footprint HDR-TH_3P-P2.54-H-M-W10.4-N
pins: 1, 2, 3

## jvj100v22m6x8
designator C??  (value not drawn)
容值:22uF;精度:±20%;额定电压:100V;纹波电流:60mA@120Hz;; Manufacturer: JIERR(捷而瑞); AddInBom: yes; ModelId: ccbda52dceed4b139172c40f75c9da3f; ModelName: CAP-SMD_BD6.3-L6.6-W6.6-LS7.3-FD-H7.7; ModelTransform: 287.401,259.842,0,0,0,0,0,0,0; Value: 22uF; Tolerance: ±20%; Voltage Rating: 100V; Lifetime: 2000hrs@105℃
footprint CAP-SMD_BD6.3-L6.6-W6.6-LS7.3-FD-H7.7
pins: 1, 2

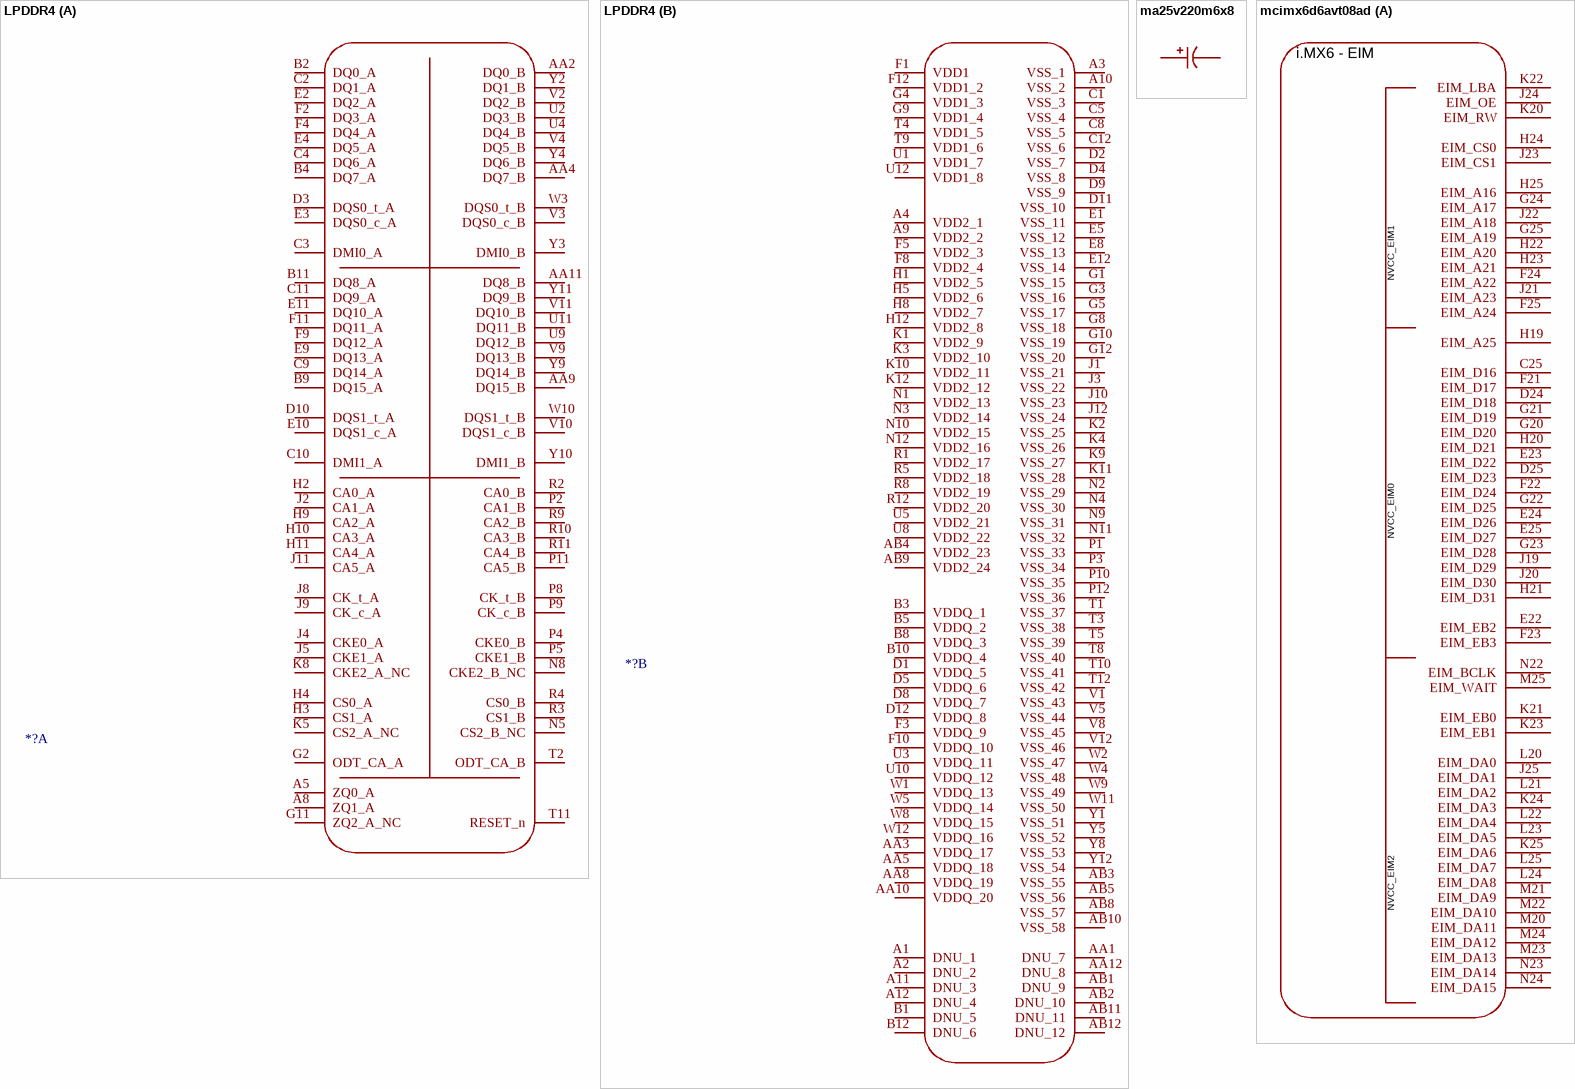
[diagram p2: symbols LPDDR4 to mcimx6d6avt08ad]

## LPDDR4
designator *?  (value not drawn)
part A pins: A5 ZQ0_A, A8 ZQ1_A, AA2 DQ0_B, AA4 DQ7_B, AA9 DQ15_B, AA11 DQ8_B, B2 DQ0_A, B4 DQ7_A, B9 DQ15_A, B11 DQ8_A, C2 DQ1_A, C3 DMI0_A, C4 DQ6_A, C9 DQ14_A, C10 DMI1_A, C11 DQ9_A, D3 DQS0_t_A, D10 DQS1_t_A, E2 DQ2_A, E3 DQS0_c_A, E4 DQ5_A, E9 DQ13_A, E10 DQS1_c_A, E11 DQ10_A, F2 DQ3_A, F4 DQ4_A, F9 DQ12_A, F11 DQ11_A, G2 ODT_CA_A, G11 ZQ2_A_NC, H2 CA0_A, H3 CS1_A, H4 CS0_A, H9 CA2_A, H10 CA3_A, H11 CA4_A, J2 CA1_A, J4 CKE0_A, J5 CKE1_A, J8 CK_t_A, J9 CK_c_A, J11 CA5_A, K5 CS2_A_NC, K8 CKE2_A_NC, N5 CS2_B_NC, N8 CKE2_B_NC, P2 CA1_B, P4 CKE0_B, P5 CKE1_B, P8 CK_t_B, P9 CK_c_B, P11 CA5_B, R2 CA0_B, R3 CS1_B, R4 CS0_B, R9 CA2_B, R10 CA3_B, R11 CA4_B, T2 ODT_CA_B, T11 RESET_n, U2 DQ3_B, U4 DQ4_B, U9 DQ12_B, U11 DQ11_B, V2 DQ2_B, V3 DQS0_c_B, V4 DQ5_B, V9 DQ13_B, V10 DQS1_c_B, V11 DQ10_B, W3 DQS0_t_B, W10 DQS1_t_B, Y2 DQ1_B, Y3 DMI0_B, Y4 DQ6_B, Y9 DQ14_B, Y10 DMI1_B, Y11 DQ9_B
part B pins: A1 DNU_1, A2 DNU_2, A3 VSS_1, A4 VDD2_1, A9 VDD2_2, A10 VSS_2, A11 DNU_3, A12 DNU_4, AA1 DNU_7, AA3 VDDQ_17, AA5 VDDQ_18, AA8 VDDQ_19, AA10 VDDQ_20, AA12 DNU_8, AB1 DNU_9, AB2 DNU_10, AB3 VSS_55, AB4 VDD2_23, AB5 VSS_56, AB8 VSS_57, AB9 VDD2_24, AB10 VSS_58, AB11 DNU_11, AB12 DNU_12, B1 DNU_5, B3 VDDQ_1, B5 VDDQ_2, B8 VDDQ_3, B10 VDDQ_4, B12 DNU_6, C1 VSS_3, C5 VSS_4, C8 VSS_5, C12 VSS_6, D1 VDDQ_5, D2 VSS_7, D4 VSS_8, D5 VDDQ_6, D8 VDDQ_7, D9 VSS_9, D11 VSS_10, D12 VDDQ_8, E1 VSS_11, E5 VSS_12, E8 VSS_13, E12 VSS_14, F1 VDD1, F3 VDDQ_9, F5 VDD2_3, F8 VDD2_4, F10 VDDQ_10, F12 VDD1_2, G1 VSS_15, G3 VSS_16, G4 VDD1_3, G5 VSS_17, G8 VSS_18, G9 VDD1_4, G10 VSS_19, G12 VSS_20, H1 VDD2_5, H5 VDD2_6, H8 VDD2_7, H12 VDD2_8, J1 VSS_21, J3 VSS_22, J10 VSS_23, J12 VSS_24, K1 VDD2_9, K2 VSS_25, K3 VDD2_10, K4 VSS_26, K9 VSS_27, K10 VDD2_11, K11 VSS_28, K12 VDD2_12, N1 VDD2_13, N2 VSS_29, N3 VDD2_14, N4 VSS_30, N9 VSS_31, N10 VDD2_15, N11 VSS_32, N12 VDD2_16, P1 VSS_33, P3 VSS_34, P10 VSS_35, P12 VSS_36, R1 VDD2_17, R5 VDD2_18, R8 VDD2_19, R12 VDD2_20, T1 VSS_37, T3 VSS_38, T4 VDD1_5, T5 VSS_39, T8 VSS_40, T9 VDD1_6, T10 VSS_41, T12 VSS_42, U1 VDD1_7, U3 VDDQ_11, U5 VDD2_21, U8 VDD2_22, U10 VDDQ_12, U12 VDD1_8, V1 VSS_43, V5 VSS_44, V8 VSS_45, V12 VSS_46, W1 VDDQ_13, W2 VSS_47, W4 VSS_48, W5 VDDQ_14, W8 VDDQ_15, W9 VSS_49, W11 VSS_50, W12 VDDQ_16, Y1 VSS_51, Y5 VSS_52, Y8 VSS_53, Y12 VSS_54

## ma25v220m6x8
designator C??  (value not drawn)
容值:220uF;精度:±20%;额定电压:25V;纹波电流:2.9A@100kHz;等效串联电阻(ESR):28mΩ@100kHz;类型:聚合物;; Manufacturer: JIERR(捷而瑞); AddInBom: yes; ModelId: 697a8c63e3274188b68c96045bc3ea1c; ModelName: CAP-SMD_BD6.3-L6.6-W6.6-LS7.3-FD; ModelTransform: 287.401,259.842,0,180,0,0,0.001,0.001,0; Value: 220uF; Tolerance: ±20%; Voltage Rating: 25V; Type: 聚合物; Lifetime: 2000hrs@105℃
footprint CAP-SMD_BD6.3-L6.6-W6.6-LS7.3-FD
pins: 1, 2

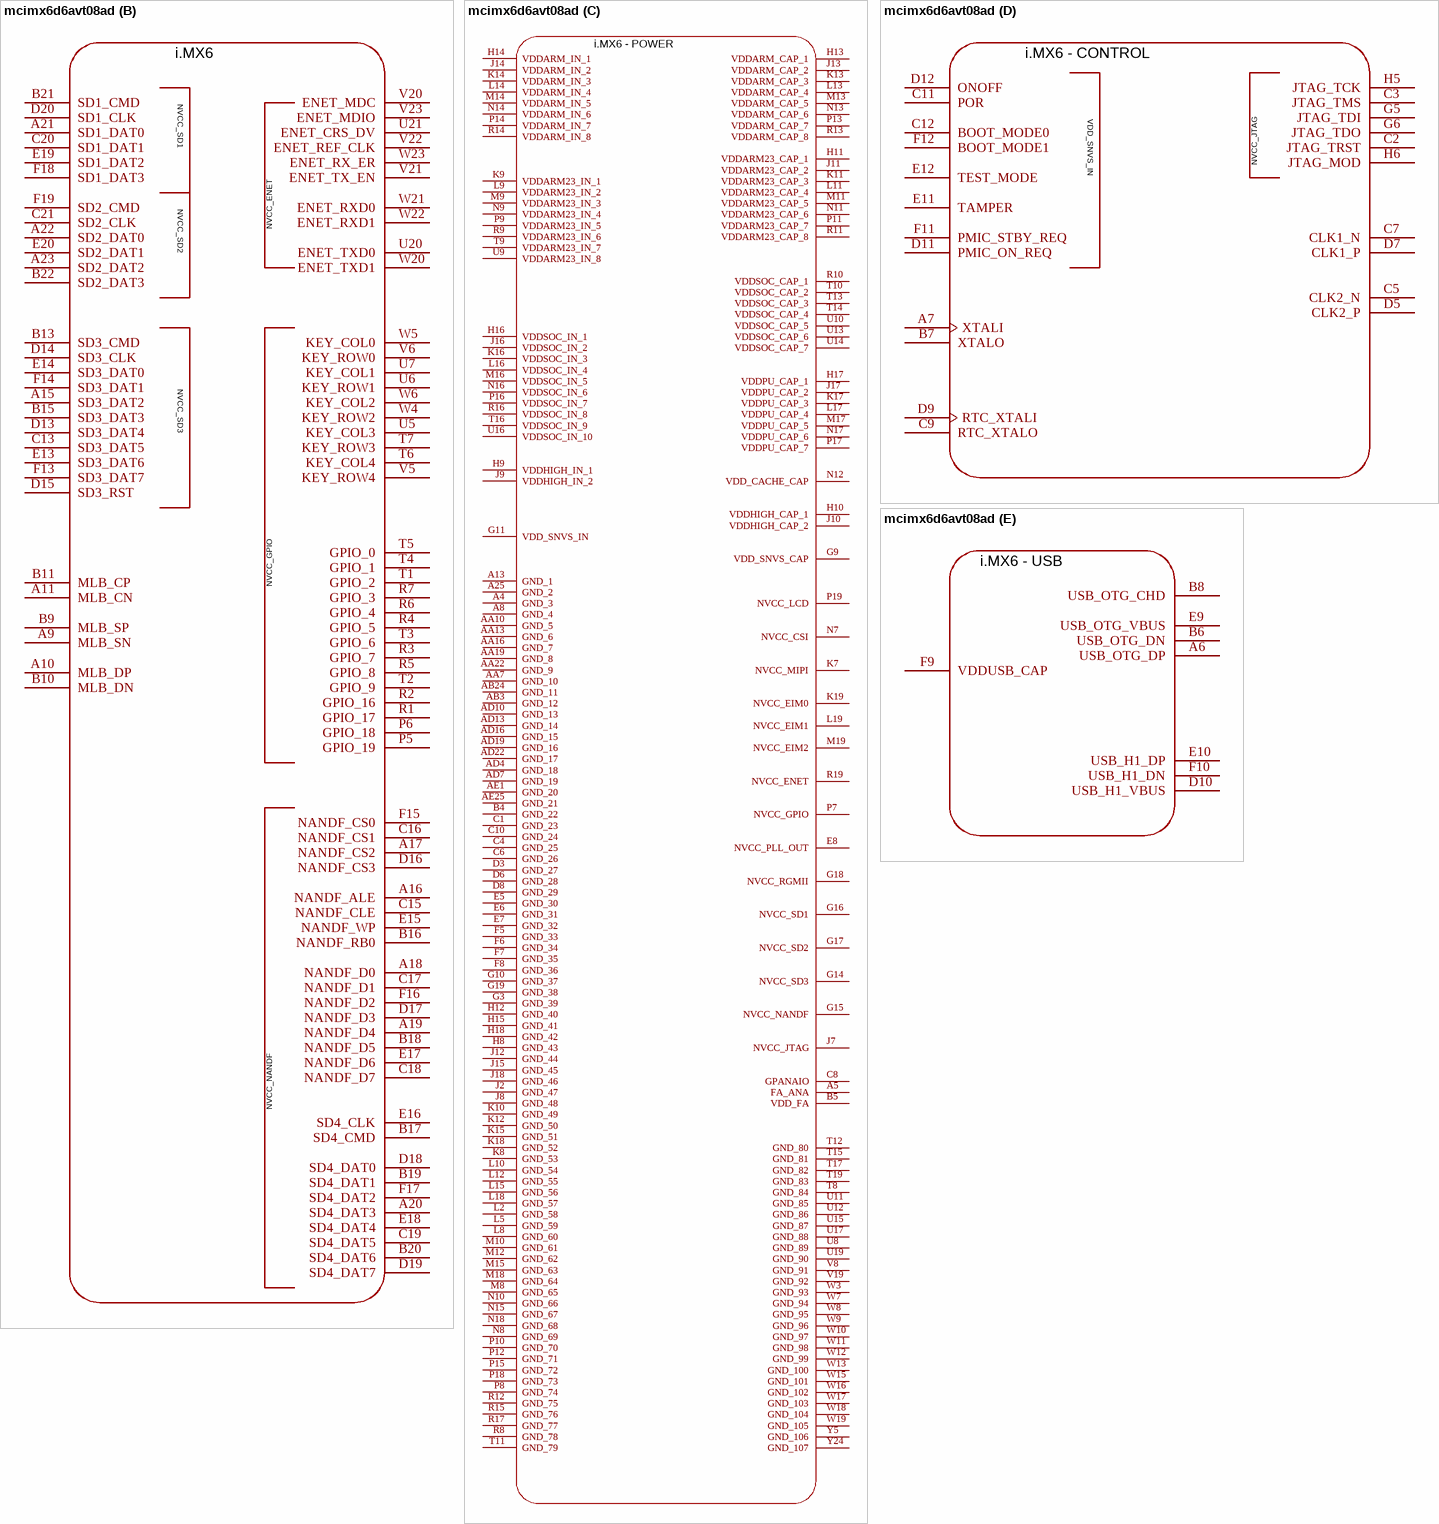
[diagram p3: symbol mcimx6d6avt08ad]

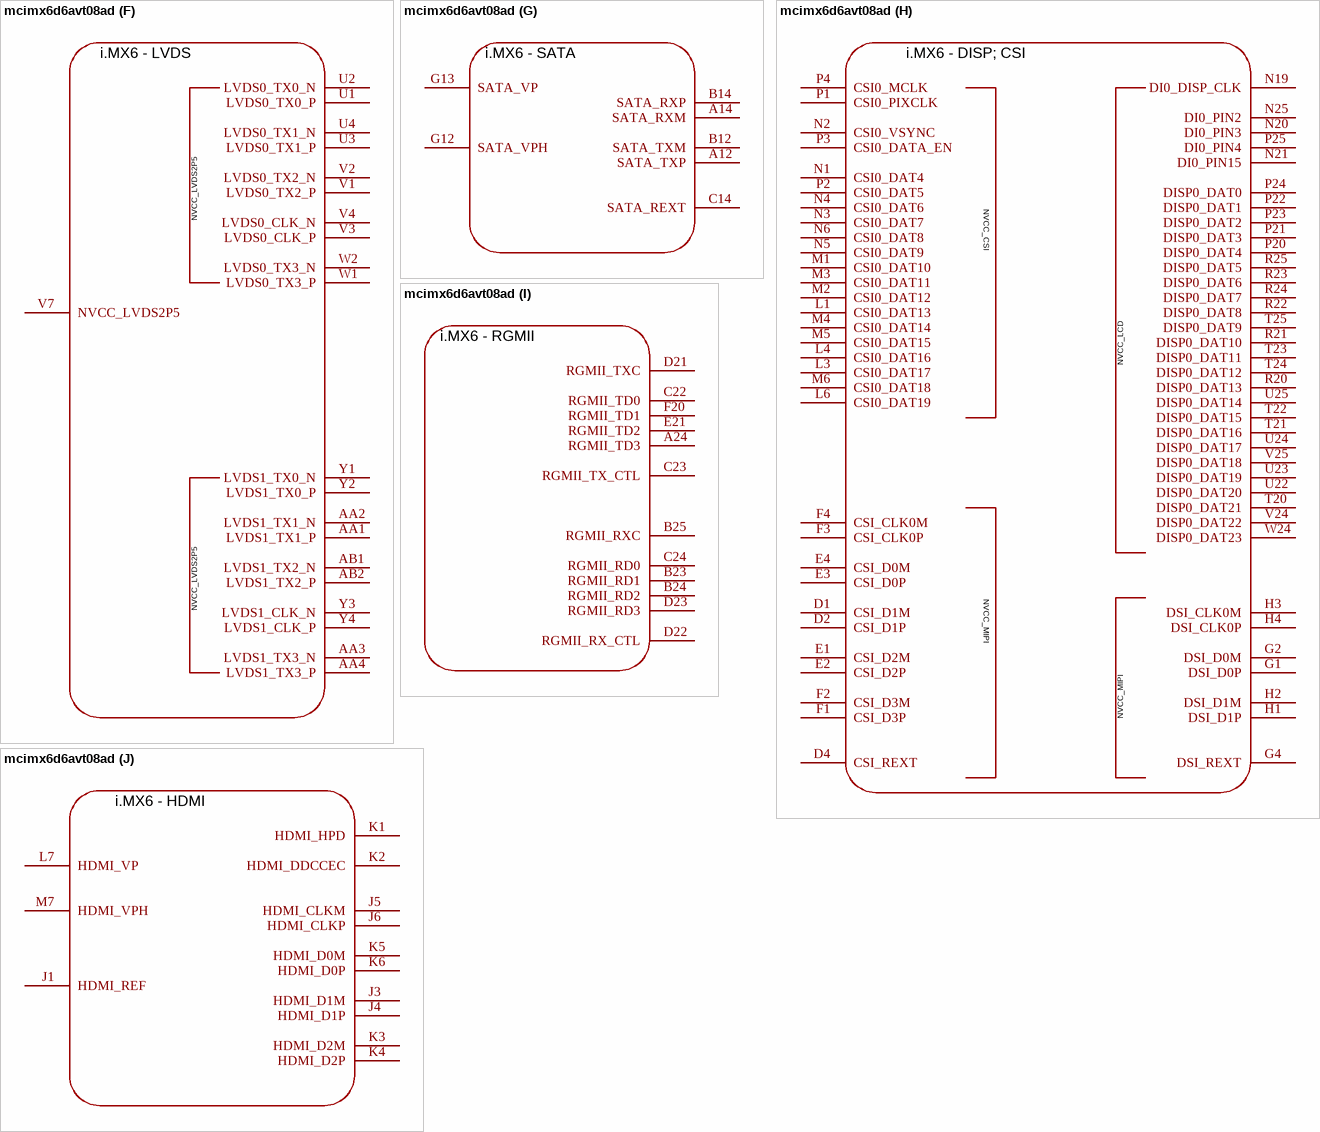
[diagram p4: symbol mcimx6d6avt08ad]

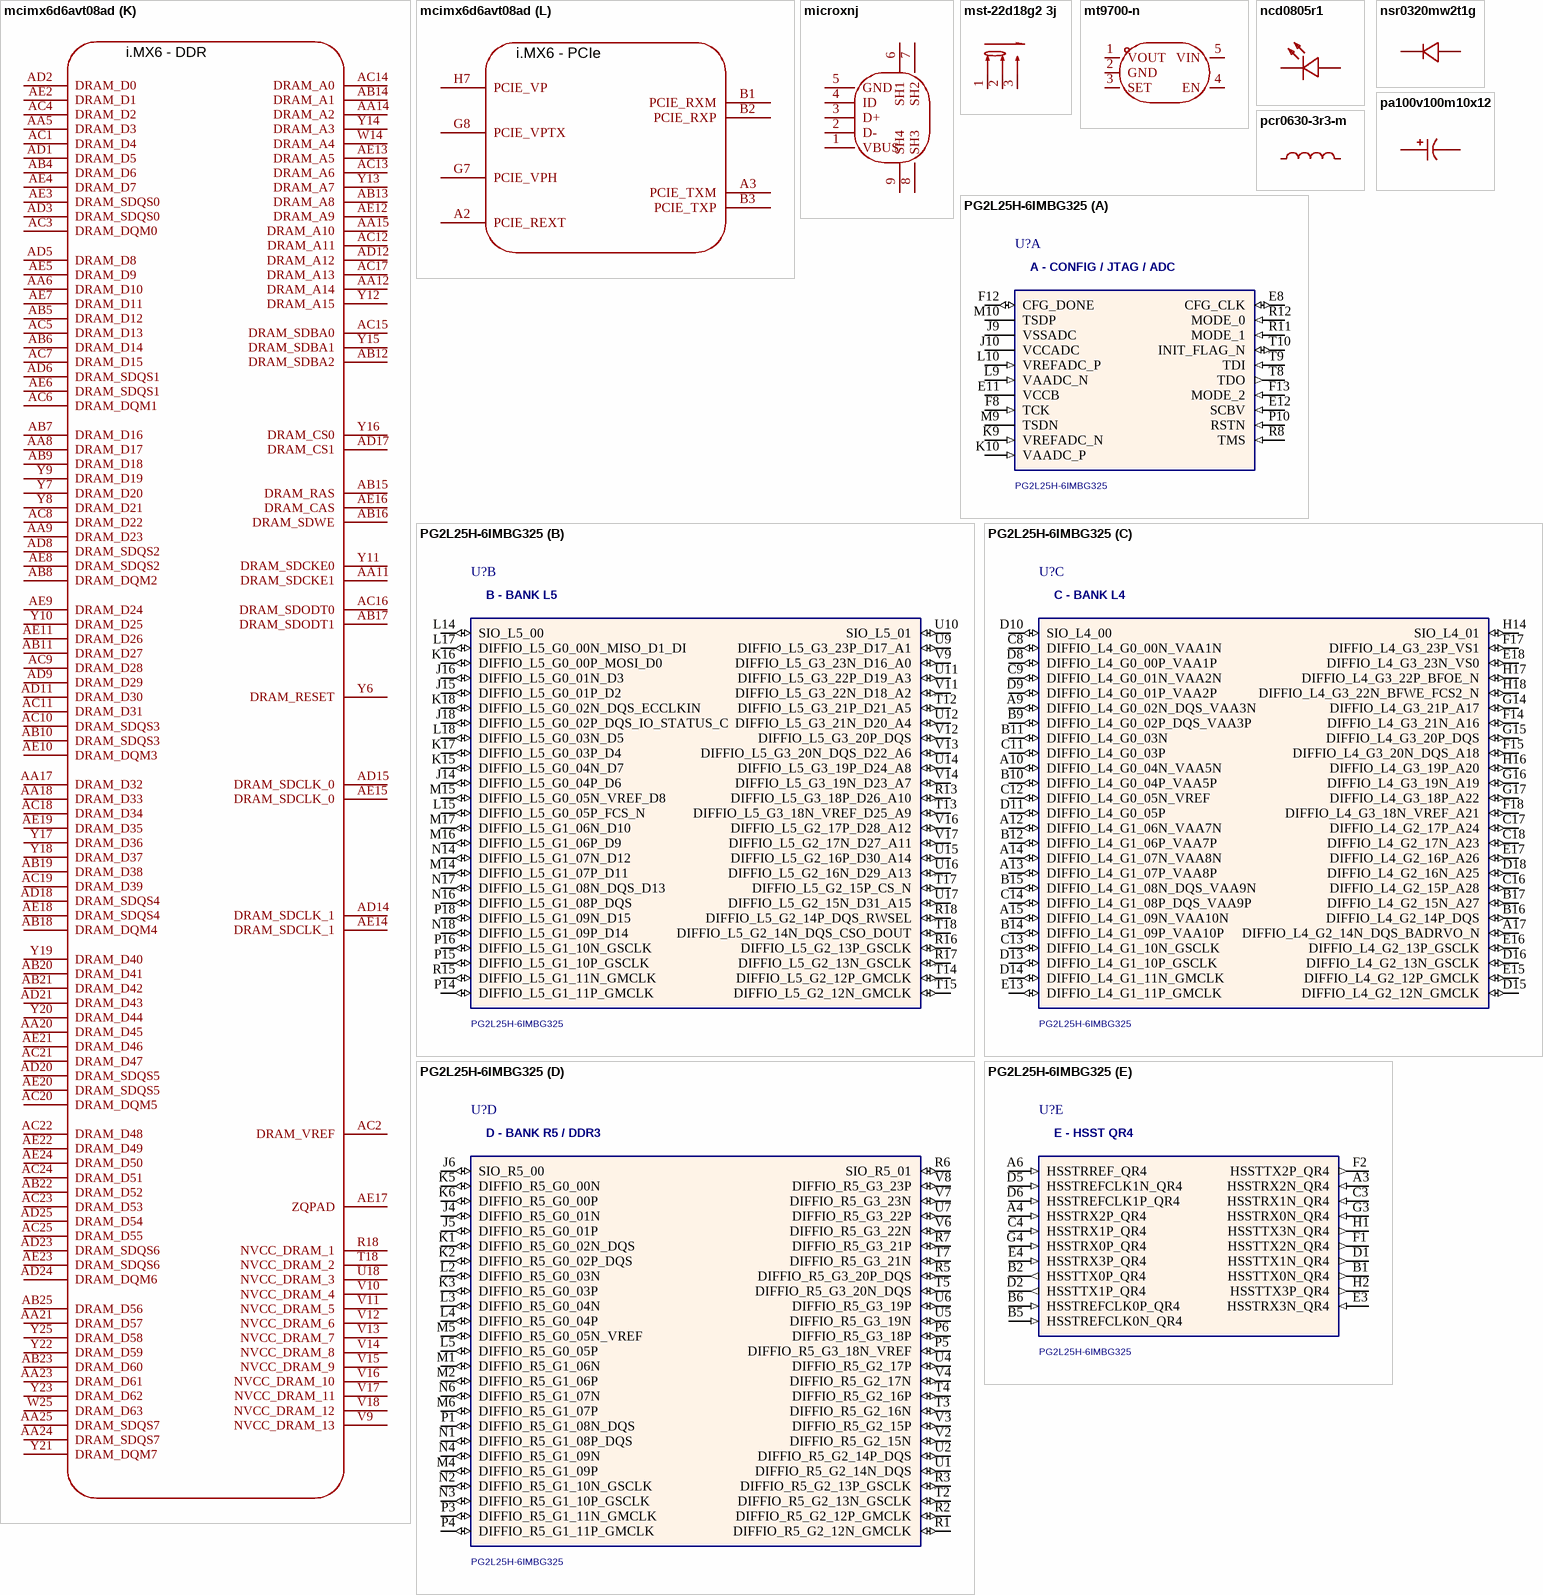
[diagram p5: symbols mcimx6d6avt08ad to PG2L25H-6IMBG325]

## mcimx6d6avt08ad
designator U??  (value not drawn)
CPU内核:ARM-A系列;CPU最大主频:852MHz;应用领域:-;; Manufacturer: NXP(恩智浦); AddInBom: yes; ModelId: e53686c3bd9346ad8f7d124605974c31; ModelName: FCPBGA-624_L21.0-W21.0-R25-C25-P0.80-TL-PE_A1; ModelTransform: 826.77,826.77,0,0,0,0,0,0,0; CPU Maximum Speed: 852MHz
footprint FCPBGA-624_L21.0-W21.0-R25-C25-P0.80-TL-PE_A1
part A pins: C25 EIM_D16, D24 EIM_D18, D25 EIM_D23, E22 EIM_EB2, E23 EIM_D22, E24 EIM_D26, E25 EIM_D27, F21 EIM_D17, F22 EIM_D24, F23 EIM_EB3, F24 EIM_A22, F25 EIM_A24, G20 EIM_D20, G21 EIM_D19, G22 EIM_D25, G23 EIM_D28, G24 EIM_A17, G25 EIM_A19, H19 EIM_A25, H20 EIM_D21, H21 EIM_D31, H22 EIM_A20, H23 EIM_A21, H24 EIM_CS0, H25 EIM_A16, J19 EIM_D29, J20 EIM_D30, J21 EIM_A23, J22 EIM_A18, J23 EIM_CS1, J24 EIM_OE, J25 EIM_DA1, K20 EIM_RW, K21 EIM_EB0, K22 EIM_LBA, K23 EIM_EB1, K24 EIM_DA3, K25 EIM_DA6, L20 EIM_DA0, L21 EIM_DA2, L22 EIM_DA4, L23 EIM_DA5, L24 EIM_DA8, L25 EIM_DA7, M20 EIM_DA11, M21 EIM_DA9, M22 EIM_DA10, M23 EIM_DA13, M24 EIM_DA12, M25 EIM_WAIT, N22 EIM_BCLK, N23 EIM_DA14, N24 EIM_DA15
part B pins: A9 MLB_SN, A10 MLB_DP, A11 MLB_CN, A15 SD3_DAT2, A16 NANDF_ALE, A17 NANDF_CS2, A18 NANDF_D0, A19 NANDF_D4, A20 SD4_DAT3, A21 SD1_DAT0, A22 SD2_DAT0, A23 SD2_DAT2, B9 MLB_SP, B10 MLB_DN, B11 MLB_CP, B13 SD3_CMD, B15 SD3_DAT3, B16 NANDF_RB0, B17 SD4_CMD, B18 NANDF_D5, B19 SD4_DAT1, B20 SD4_DAT6, B21 SD1_CMD, B22 SD2_DAT3, C13 SD3_DAT5, C15 NANDF_CLE, C16 NANDF_CS1, C17 NANDF_D1, C18 NANDF_D7, C19 SD4_DAT5, C20 SD1_DAT1, C21 SD2_CLK, D13 SD3_DAT4, D14 SD3_CLK, D15 SD3_RST, D16 NANDF_CS3, D17 NANDF_D3, D18 SD4_DAT0, D19 SD4_DAT7, D20 SD1_CLK, E13 SD3_DAT6, E14 SD3_DAT0, E15 NANDF_WP, E16 SD4_CLK, E17 NANDF_D6, E18 SD4_DAT4, E19 SD1_DAT2, E20 SD2_DAT1, F13 SD3_DAT7, F14 SD3_DAT1, F15 NANDF_CS0, F16 NANDF_D2, F17 SD4_DAT2, F18 SD1_DAT3, F19 SD2_CMD, P5 GPIO_19, P6 GPIO_18, R1 GPIO_17, R2 GPIO_16, R3 GPIO_7, R4 GPIO_5, R5 GPIO_8, R6 GPIO_4, R7 GPIO_3, T1 GPIO_2, T2 GPIO_9, T3 GPIO_6, T4 GPIO_1, T5 GPIO_0, T6 KEY_COL4, T7 KEY_ROW3, U5 KEY_COL3, U6 KEY_ROW1, U7 KEY_COL1, U20 ENET_TXD0, U21 ENET_CRS_DV, V5 KEY_ROW4, V6 KEY_ROW0, V20 ENET_MDC, V21 ENET_TX_EN, V22 ENET_REF_CLK, V23 ENET_MDIO, W4 KEY_ROW2, W5 KEY_COL0, W6 KEY_COL2, W20 ENET_TXD1, W21 ENET_RXD0, W22 ENET_RXD1, W23 ENET_RX_ER
part C pins: A4 GND_3, A5 FA_ANA, A8 GND_4, A13 GND_1, A25 GND_2, AA7 GND_10, AA10 GND_5, AA13 GND_6, AA16 GND_7, AA19 GND_8, AA22 GND_9, AB3 GND_12, AB24 GND_11, AD4 GND_18, AD7 GND_19, AD10 GND_13, AD13 GND_14, AD16 GND_15, AD19 GND_16, AD22 GND_17, AE1 GND_20, AE25 GND_21, B4 GND_22, B5 VDD_FA, C1 GND_23, C4 GND_25, C6 GND_26, C8 GPANAIO, C10 GND_24, D3 GND_27, D6 GND_28, D8 GND_29, E5 GND_30, E6 GND_31, E7 GND_32, E8 NVCC_PLL_OUT, F5 GND_33, F6 GND_34, F7 GND_35, F8 GND_36, G3 GND_39, G9 VDD_SNVS_CAP, G10 GND_37, G11 VDD_SNVS_IN, G14 NVCC_SD3, G15 NVCC_NANDF, G16 NVCC_SD1, G17 NVCC_SD2, G18 NVCC_RGMII, G19 GND_38, H8 GND_43, H9 VDDHIGH_IN_1, H10 VDDHIGH_CAP_1, H11 VDDARM23_CAP_1, H12 GND_40, H13 VDDARM_CAP_1, H14 VDDARM_IN_1, H15 GND_41, H16 VDDSOC_IN_1, H17 VDDPU_CAP_1, H18 GND_42, J2 GND_47, J7 NVCC_JTAG, J8 GND_48, J9 VDDHIGH_IN_2, J10 VDDHIGH_CAP_2, J11 VDDARM23_CAP_2, J12 GND_44, J13 VDDARM_CAP_2, J14 VDDARM_IN_2, J15 GND_45, J16 VDDSOC_IN_2, J17 VDDPU_CAP_2, J18 GND_46, K7 NVCC_MIPI, K8 GND_53, K9 VDDARM23_IN_1, K10 GND_49, K11 VDDARM23_CAP_3, K12 GND_50, K13 VDDARM_CAP_3, K14 VDDARM_IN_3, K15 GND_51, K16 VDDSOC_IN_3, K17 VDDPU_CAP_3, K18 GND_52, K19 NVCC_EIM0, L2 GND_58, L5 GND_59, L8 GND_60, L9 VDDARM23_IN_2, L10 GND_54, L11 VDDARM23_CAP_4, L12 GND_55, L13 VDDARM_CAP_4, L14 VDDARM_IN_4, L15 GND_56, L16 VDDSOC_IN_4, L17 VDDPU_CAP_4, L18 GND_57, L19 NVCC_EIM1, M8 GND_65, M9 VDDARM23_IN_3, M10 GND_61, M11 VDDARM23_CAP_5, M12 GND_62, M13 VDDARM_CAP_5, M14 VDDARM_IN_5, M15 GND_63, M16 VDDSOC_IN_5, M17 VDDPU_CAP_5, M18 GND_64, M19 NVCC_EIM2, N7 NVCC_CSI, N8 GND_69, N9 VDDARM23_IN_4, N10 GND_66, N11 VDDARM23_CAP_6, N12 VDD_CACHE_CAP, N13 VDDARM_CAP_6, N14 VDDARM_IN_6, N15 GND_67, N16 VDDSOC_IN_6, N17 VDDPU_CAP_6, N18 GND_68, P7 NVCC_GPIO, P8 GND_74, P9 VDDARM23_IN_5, P10 GND_70, P11 VDDARM23_CAP_7, P12 GND_71, P13 VDDARM_CAP_7, P14 VDDARM_IN_7, P15 GND_72, P16 VDDSOC_IN_7, P17 VDDPU_CAP_7, P18 GND_73, P19 NVCC_LCD, R8 GND_78, R9 VDDARM23_IN_6, R10 VDDSOC_CAP_1, R11 VDDARM23_CAP_8, R12 GND_75, R13 VDDARM_CAP_8, R14 VDDARM_IN_8, R15 GND_76, R16 VDDSOC_IN_8, R17 GND_77, R19 NVCC_ENET, T8 GND_84, T9 VDDARM23_IN_7, T10 VDDSOC_CAP_2, T11 GND_79, T12 GND_80, T13 VDDSOC_CAP_3, T14 VDDSOC_CAP_4, T15 GND_81, T16 VDDSOC_IN_9, T17 GND_82, T19 GND_83, U8 GND_89, U9 VDDARM23_IN_8, U10 VDDSOC_CAP_5, U11 GND_85, U12 GND_86, U13 VDDSOC_CAP_6, U14 VDDSOC_CAP_7, U15 GND_87, U16 VDDSOC_IN_10, U17 GND_88, U19 GND_90, V8 GND_91, V19 GND_92, W3 GND_93, W7 GND_94, W8 GND_95, W9 GND_96, W10 GND_97, W11 GND_98, W12 GND_99, W13 GND_100, W15 GND_101, W16 GND_102, W17 GND_103, W18 GND_104, W19 GND_105, Y5 GND_106, Y24 GND_107
part D pins: A7 XTALI, B7 XTALO, C2 JTAG_TRST, C3 JTAG_TMS, C5 CLK2_N, C7 CLK1_N, C9 RTC_XTALO, C11 POR, C12 BOOT_MODE0, D5 CLK2_P, D7 CLK1_P, D9 RTC_XTALI, D11 PMIC_ON_REQ, D12 ONOFF, E11 TAMPER, E12 TEST_MODE, F11 PMIC_STBY_REQ, F12 BOOT_MODE1, G5 JTAG_TDI, G6 JTAG_TDO, H5 JTAG_TCK, H6 JTAG_MOD
part E pins: A6 USB_OTG_DP, B6 USB_OTG_DN, B8 USB_OTG_CHD, D10 USB_H1_VBUS, E9 USB_OTG_VBUS, E10 USB_H1_DP, F9 VDDUSB_CAP, F10 USB_H1_DN
part F pins: AA1 LVDS1_TX1_P, AA2 LVDS1_TX1_N, AA3 LVDS1_TX3_N, AA4 LVDS1_TX3_P, AB1 LVDS1_TX2_N, AB2 LVDS1_TX2_P, U1 LVDS0_TX0_P, U2 LVDS0_TX0_N, U3 LVDS0_TX1_P, U4 LVDS0_TX1_N, V1 LVDS0_TX2_P, V2 LVDS0_TX2_N, V3 LVDS0_CLK_P, V4 LVDS0_CLK_N, V7 NVCC_LVDS2P5, W1 LVDS0_TX3_P, W2 LVDS0_TX3_N, Y1 LVDS1_TX0_N, Y2 LVDS1_TX0_P, Y3 LVDS1_CLK_N, Y4 LVDS1_CLK_P
part G pins: A12 SATA_TXP, A14 SATA_RXM, B12 SATA_TXM, B14 SATA_RXP, C14 SATA_REXT, G12 SATA_VPH, G13 SATA_VP
part H pins: D1 CSI_D1M, D2 CSI_D1P, D4 CSI_REXT, E1 CSI_D2M, E2 CSI_D2P, E3 CSI_D0P, E4 CSI_D0M, F1 CSI_D3P, F2 CSI_D3M, F3 CSI_CLK0P, F4 CSI_CLK0M, G1 DSI_D0P, G2 DSI_D0M, G4 DSI_REXT, H1 DSI_D1P, H2 DSI_D1M, H3 DSI_CLK0M, H4 DSI_CLK0P, L1 CSI0_DAT13, L3 CSI0_DAT17, L4 CSI0_DAT16, L6 CSI0_DAT19, M1 CSI0_DAT10, M2 CSI0_DAT12, M3 CSI0_DAT11, M4 CSI0_DAT14, M5 CSI0_DAT15, M6 CSI0_DAT18, N1 CSI0_DAT4, N2 CSI0_VSYNC, N3 CSI0_DAT7, N4 CSI0_DAT6, N5 CSI0_DAT9, N6 CSI0_DAT8, N19 DI0_DISP_CLK, N20 DI0_PIN3, N21 DI0_PIN15, N25 DI0_PIN2, P1 CSI0_PIXCLK, P2 CSI0_DAT5, P3 CSI0_DATA_EN, P4 CSI0_MCLK, P20 DISP0_DAT4, P21 DISP0_DAT3, P22 DISP0_DAT1, P23 DISP0_DAT2, P24 DISP0_DAT0, P25 DI0_PIN4, R20 DISP0_DAT13, R21 DISP0_DAT10, R22 DISP0_DAT8, R23 DISP0_DAT6, R24 DISP0_DAT7, R25 DISP0_DAT5, T20 DISP0_DAT21, T21 DISP0_DAT16, T22 DISP0_DAT15, T23 DISP0_DAT11, T24 DISP0_DAT12, T25 DISP0_DAT9, U22 DISP0_DAT20, U23 DISP0_DAT19, U24 DISP0_DAT17, U25 DISP0_DAT14, V24 DISP0_DAT22, V25 DISP0_DAT18, W24 DISP0_DAT23
part I pins: A24 RGMII_TD3, B23 RGMII_RD1, B24 RGMII_RD2, B25 RGMII_RXC, C22 RGMII_TD0, C23 RGMII_TX_CTL, C24 RGMII_RD0, D21 RGMII_TXC, D22 RGMII_RX_CTL, D23 RGMII_RD3, E21 RGMII_TD2, F20 RGMII_TD1
part J pins: J1 HDMI_REF, J3 HDMI_D1M, J4 HDMI_D1P, J5 HDMI_CLKM, J6 HDMI_CLKP, K1 HDMI_HPD, K2 HDMI_DDCCEC, K3 HDMI_D2M, K4 HDMI_D2P, K5 HDMI_D0M, K6 HDMI_D0P, L7 HDMI_VP, M7 HDMI_VPH
part K pins: AA5 DRAM_D3, AA6 DRAM_D10, AA8 DRAM_D17, AA9 DRAM_D23, AA11 DRAM_SDCKE1, AA12 DRAM_A14, AA14 DRAM_A2, AA15 DRAM_A10, AA17 DRAM_D32, AA18 DRAM_D33, AA20 DRAM_D45, AA21 DRAM_D57, AA23 DRAM_D61, AA24 DRAM_SDQS7, AA25 DRAM_SDQS7, AB4 DRAM_D6, AB5 DRAM_D12, AB6 DRAM_D14, AB7 DRAM_D16, AB8 DRAM_DQM2, AB9 DRAM_D18, AB10 DRAM_SDQS3, AB11 DRAM_D27, AB12 DRAM_SDBA2, AB13 DRAM_A8, AB14 DRAM_A1, AB15 DRAM_RAS, AB16 DRAM_SDWE, AB17 DRAM_SDODT1, AB18 DRAM_DQM4, AB19 DRAM_D38, AB20 DRAM_D41, AB21 DRAM_D42, AB22 DRAM_D52, AB23 DRAM_D60, AB25 DRAM_D56, AC1 DRAM_D4, AC2 DRAM_VREF, AC3 DRAM_DQM0, AC4 DRAM_D2, AC5 DRAM_D13, AC6 DRAM_DQM1, AC7 DRAM_D15, AC8 DRAM_D22, AC9 DRAM_D28, AC10 DRAM_SDQS3, AC11 DRAM_D31, AC12 DRAM_A11, AC13 DRAM_A6, AC14 DRAM_A0, AC15 DRAM_SDBA0, AC16 DRAM_SDODT0, AC17 DRAM_A13, AC18 DRAM_D34, AC19 DRAM_D39, AC20 DRAM_DQM5, AC21 DRAM_D47, AC22 DRAM_D48, AC23 DRAM_D53, AC24 DRAM_D51, AC25 DRAM_D55, AD1 DRAM_D5, AD2 DRAM_D0, AD3 DRAM_SDQS0, AD5 DRAM_D8, AD6 DRAM_SDQS1, AD8 DRAM_SDQS2, AD9 DRAM_D29, AD11 DRAM_D30, AD12 DRAM_A12, AD14 DRAM_SDCLK_1, AD15 DRAM_SDCLK_0, AD17 DRAM_CS1, AD18 DRAM_SDQS4, AD20 DRAM_SDQS5, AD21 DRAM_D43, AD23 DRAM_SDQS6, AD24 DRAM_DQM6, AD25 DRAM_D54, AE2 DRAM_D1, AE3 DRAM_SDQS0, AE4 DRAM_D7, AE5 DRAM_D9, AE6 DRAM_SDQS1, AE7 DRAM_D11, AE8 DRAM_SDQS2, AE9 DRAM_D24, AE10 DRAM_DQM3, AE11 DRAM_D26, AE12 DRAM_A9, AE13 DRAM_A5, AE14 DRAM_SDCLK_1, AE15 DRAM_SDCLK_0, AE16 DRAM_CAS, AE17 ZQPAD, AE18 DRAM_SDQS4, AE19 DRAM_D35, AE20 DRAM_SDQS5, AE21 DRAM_D46, AE22 DRAM_D49, AE23 DRAM_SDQS6, AE24 DRAM_D50, R18 NVCC_DRAM_1, T18 NVCC_DRAM_2, U18 NVCC_DRAM_3, V9 NVCC_DRAM_13, V10 NVCC_DRAM_4, V11 NVCC_DRAM_5, V12 NVCC_DRAM_6, V13 NVCC_DRAM_7, V14 NVCC_DRAM_8, V15 NVCC_DRAM_9, V16 NVCC_DRAM_10, V17 NVCC_DRAM_11, V18 NVCC_DRAM_12, W14 DRAM_A4, W25 DRAM_D63, Y6 DRAM_RESET, Y7 DRAM_D20, Y8 DRAM_D21, Y9 DRAM_D19, Y10 DRAM_D25, Y11 DRAM_SDCKE0, Y12 DRAM_A15, Y13 DRAM_A7, Y14 DRAM_A3, Y15 DRAM_SDBA1, Y16 DRAM_CS0, Y17 DRAM_D36, Y18 DRAM_D37, Y19 DRAM_D40, Y20 DRAM_D44, Y21 DRAM_DQM7, Y22 DRAM_D59, Y23 DRAM_D62, Y25 DRAM_D58
part L pins: A2 PCIE_REXT, A3 PCIE_TXM, B1 PCIE_RXM, B2 PCIE_RXP, B3 PCIE_TXP, G7 PCIE_VPH, G8 PCIE_VPTX, H7 PCIE_VP

## microxnj
designator USB??  (value not drawn)
连接器类型:Micro-B;协议标准:USB 2.0;公母:母;安装方式:卧贴;触点数量:5P;端口数量:1;额定电流 - 电源:1.8A;工作温度:-30℃~+80℃;; Manufacturer: SHOU HAN(首韩); AddInBom: yes; ModelId: d71825624ed74c65b7c976fd09fd0f0f; ModelName: MICRO-USB-SMD_MICROXNJ_1; ModelTransform: 314.96,234.80992,0,90,0,0,34.256,-0.597,-35.433; Protocol Standard: USB 2.0; Gender: 母; Number of Contacts: 5P; Number of Ports: 1; Current Rating-Power: 1.8A; Voltage Rating: 30V; Connect-Disconnect Life: 2千次; Detection color: 黑色
footprint MICRO-USB-SMD_MICROXNJ_1
pins: 1 VBUS, 2 D-, 3 D+, 4 ID, 5 GND, 6 SH1, 7 SH2, 8 SH3, 9 SH4

## mst-22d18g2 3j
designator SW??  (value not drawn)
电路结构:单刀双掷;安装方式:立贴;开关颜色:黑色;额定电流:50mA;额定电压:12V;工作寿命:1万次;; Manufacturer: SHOU HAN(首韩); Symbol: MST-22D18G2 3J_C2875122; AddInBom: yes; ModelId: 05eac6dc60854b3898b1a287fa4d6e1f; ModelName: SW-SMD_SHOUHAN_MST-22D18G23J_C2875122; ModelTransform: 358.267,291.338,0,0,0,0,0,0,0; Circuit: 单刀双掷; Actuator Style: 矩形柱状; Switch Height: 5.5mm; Actuator Color: 黑色; Current Rating: 50mA; Voltage Rating: 12V; Life: 1万次
footprint SW-SMD_SHOUHAN_MST-22D18G23J_C2875122
pins: 1, 2, 3

## mt9700-n
designator U??  (value not drawn)
类型:负载开关;通道数:1;输入控制逻辑:高电平有效;工作电压:2.4V~5.5V;最大连续电流:2A;导通电阻:80mΩ;; Manufacturer: 西安航天民芯; AddInBom: yes; ModelId: f208335ea6894ff1b04bfab971ca745a; ModelName: SOT-23-5_L2.9-W1.6-P0.95-LS2.9-BL; ModelTransform: 114.173,114.173,0,0,0,0,0,-0.003,0; Number of Channels: 1; Control Input Logic: 高电平有效; Maximum Continuous Current: 2A; RDS(on): 80mΩ
footprint SOT-23-5_L2.9-W1.6-P0.95-LS2.9-BL
pins: 1 VOUT, 2 GND, 3 SET, 4 EN, 5 VIN

## ncd0805r1
designator LED??  (value not drawn)
灯头类型:-;发光颜色:红色;正向压降(Vf):1.6V~2.6V;功率:65mW;正向电流:25mA;波长:615nm~630nm;二极管配置:独立二极管;透镜颜色:-;色温:-;发光强度:195mcd;发光角度:130°;载带方式:-;工作温度:-30℃~+85℃;; Manufacturer: 国星光电; Symbol: FC-2012HRK-620D; AddInBom: yes; ModelId: b1c5ed7a4f6e46d3bc6f6cc7c20f3fea; ModelName: LED0805-RD; ModelTransform: 79.527,49.2125,0,0,0,0,0,0,0; Illumination Color: 红色; Power(Watts): 65mW; Forward Current: 25mA; Peak Wavelength: 630nm; Diode Configuration: 独立二极管; Luminous Intensity: 195mcd; Viewing Angle: 130°
footprint LED0805-RD
pins: 1 -, 2 +

## nsr0320mw2t1g
designator D??  (value not drawn)
正向压降(Vf):500mV@900mA;直流反向耐压(Vr):20V;整流电流:1A;; Manufacturer: onsemi(安森美); AddInBom: yes; ModelId: db63db13d9e342eb939127d413d6200b; ModelName: SOD-323_L1.8-W1.3-LS2.5-RD; ModelTransform: 104.3305,51.181,0,0,0,0,0,-0.004,0; Voltage - DC Reverse(Vr): 20V; Current - Rectified: 1A; Reverse Leakage Current (Ir): 50uA@15V; Operating Junction Temperature Range: -55℃~+125℃; Non-Repetitive Peak Forward Surge Current: 5A
footprint SOD-323_L1.8-W1.3-LS2.5-RD
pins: 1 C, 2 A

## pa100v100m10x12
designator C??  (value not drawn)
容值:100uF;精度:±20%;额定电压:100V;纹波电流:2.6A@100kHz;等效串联电阻(ESR):40mΩ@100kHz;类型:聚合物;; Manufacturer: JIERR(捷而瑞); AddInBom: yes; ModelId: 6de71f258d10432db69c5a71396d9b6a; ModelName: CAP-TH_BD10.0-P5.00-D0.6-FD_2; ModelTransform: 393.69921,393.73898,0,0,0,0,0,0,-196.85; Value: 100uF; Tolerance: ±20%; Voltage Rating: 100V; Type: 聚合物; Pin Spacing: 5mm; Lifetime: 2000hrs@105℃
footprint CAP-TH_BD10.0-P5.00-D0.6-FD_2
pins: 1, 2

## pcr0630-3r3-m
designator L??  (value not drawn)
合金电感 一体成型电感 大电流; Manufacturer: JIERR(捷而瑞); AddInBom: yes; ModelId: c59904d920804e3c81522e1ce8ef9eb5; ModelName: IND-SMD_L7.5-W6.6-H3.0; ModelTransform: 295.275,259.842,0,0,0,0,0,0,0
footprint IND-SMD_L7.5-W6.6
pins: 1, 2

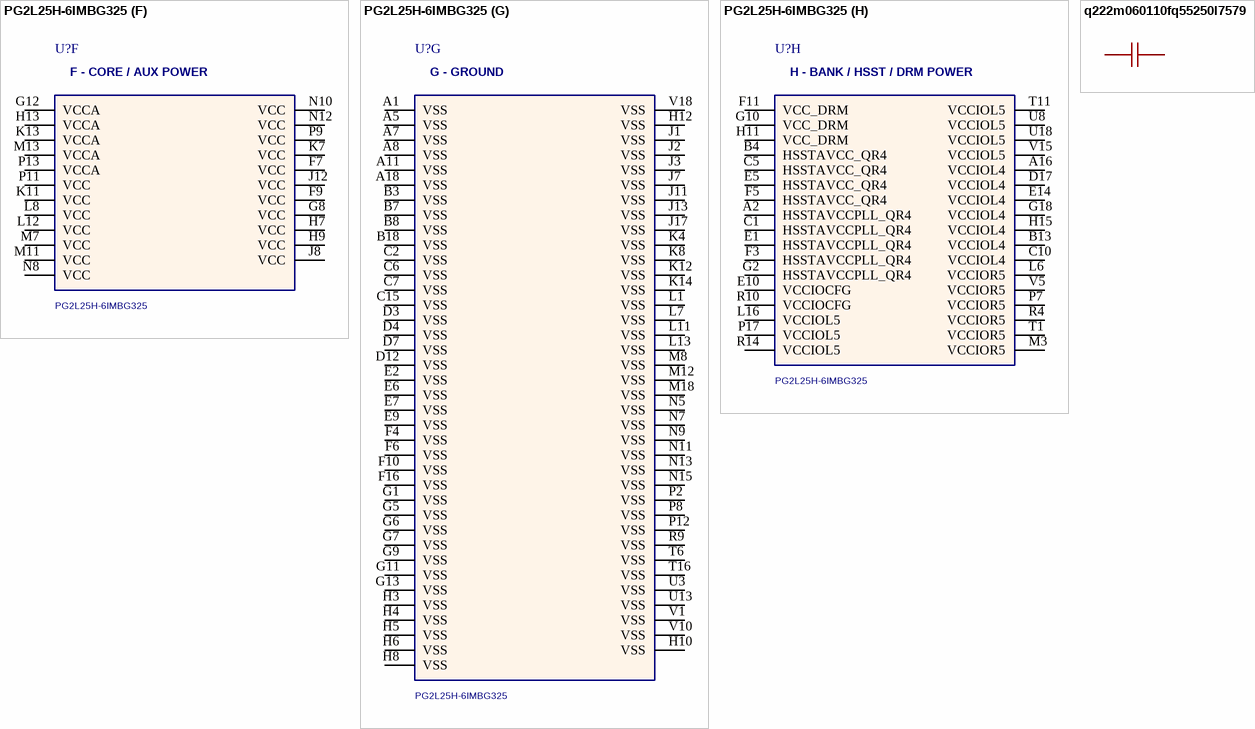
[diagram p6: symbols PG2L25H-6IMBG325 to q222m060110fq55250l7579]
